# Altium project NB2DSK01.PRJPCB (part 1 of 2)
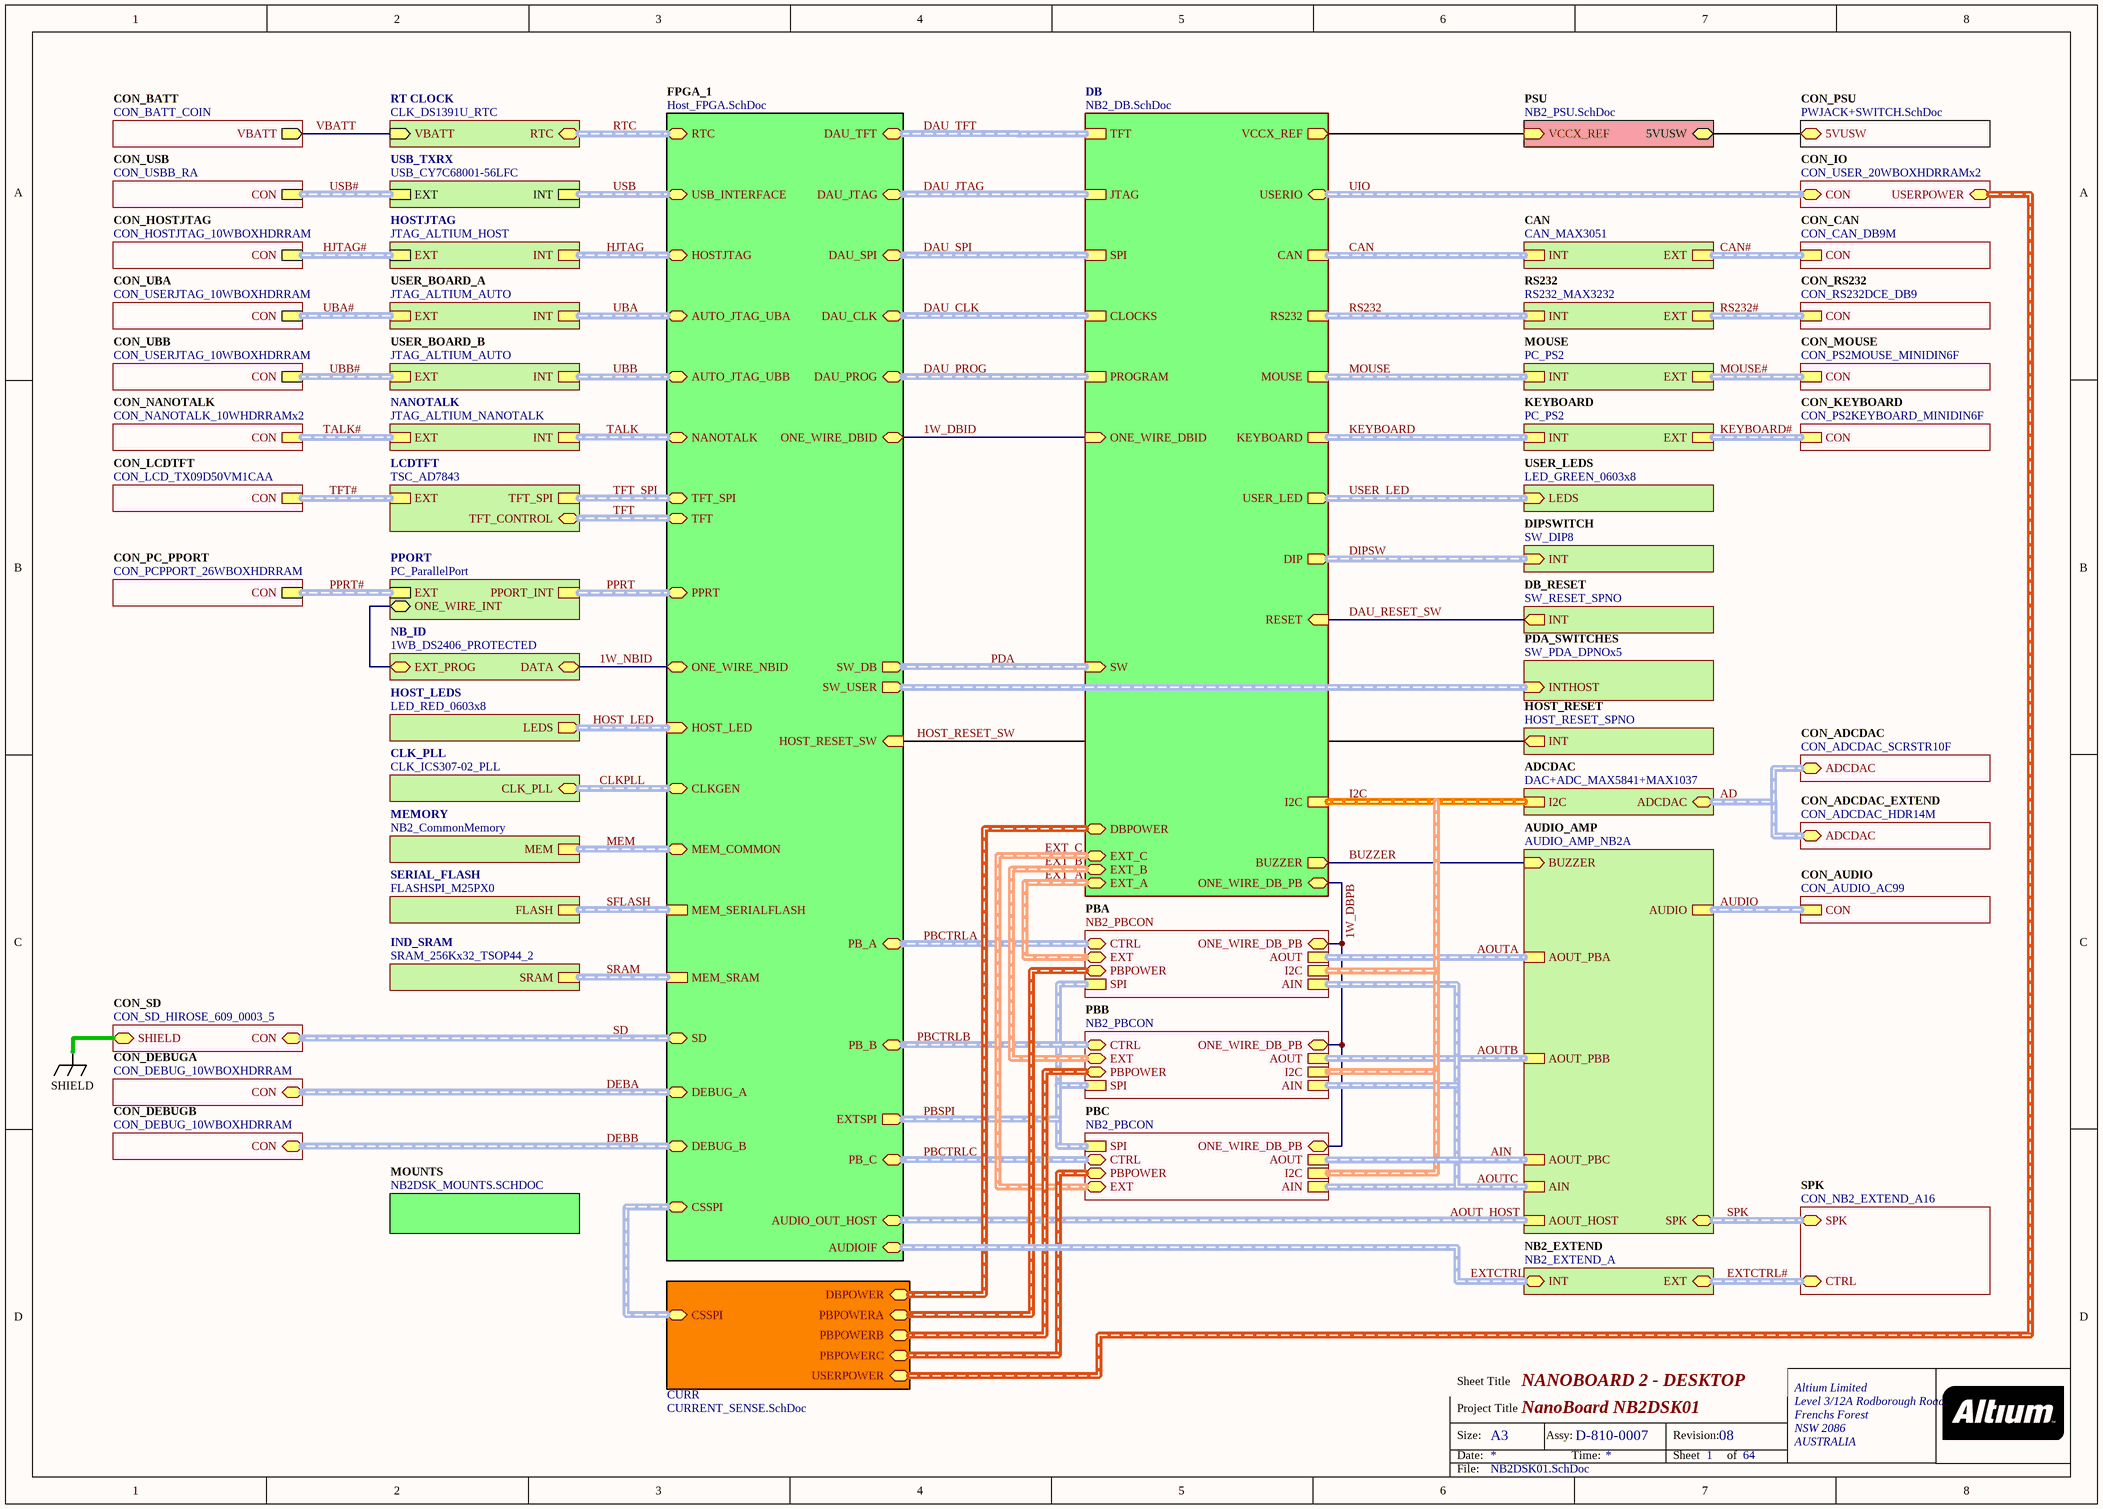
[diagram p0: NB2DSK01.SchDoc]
ProjectAddress1: Level 3/12A Rodborough Road; ProjectAddress2: Frenchs Forest; ProjectAddress3: NSW 2086; ProjectAddress4: AUSTRALIA; ProjectAssyNum: D-810-0007; ProjectOrganization: Altium Limited; ProjectRevision: 08; ProjectTitle: NanoBoard NB2DSK01; ProjectTotalSheets: 64
9 sheets, 136 parts. Net scope: hierarchical (ports join the sheet entries above them; power ports are global).
Board file: NB2DSK01.PcbDoc
Sheets:
  NB2DSK01.SchDoc
    MOUNTS = NB2DSK_Mounts.SchDoc
    PSU = NB2_PSU.SchDoc
    CON_PSU = PWJACK+SWITCH.SchDoc
    FPGA_1 = Host_FPGA.SchDoc
      FPGA_PRGSETUP_1 = FPGA_PRGSETUP.SchDoc
        XC3S1500-4FG676C_CONFIGPWR_1 = XC3S1500-4FG676C_PWRSETUP.SchDoc
    CURR = CURRENT_SENSE.SchDoc
    DB = NB2_DB.SchDoc

## Sheet NB2DSK01.SchDoc: NANOBOARD 2 - DESKTOP
size A3; Organization: Altium Limited.; Address1: Level 3, 12a Rodborough Rd; Address2: Frenchs Forest 2086; Address3: NSW; Address4: AUSTRALIA; DocumentNumber: 1; Revision: 6; SheetNumber: 1; SheetTotal: 64; PageSetup: Record=PageOptions|CenterHorizontal=True|CenterVertical=True|PrintScale=0.67|XCorrection=1.00|YCorrection=1.00|PrintKind=0|BorderSize=5000000|LeftOffset=0|BottomOffset=0|Orientation=1|PaperLength=4200|PaperWidth=2969|Scale=100|PaperSource=7|PrintQuality=1200|MediaType=1|DitherType=10|PaperKind=A4 (210 x 297 mm)|PrintScaleMode=1

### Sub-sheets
ADCDAC = DAC+ADC_MAX5841+MAX1037 (file not in this document): I2C (harness I2C), ADCDAC (harness ADCDAC)
AUDIO_AMP = AUDIO_AMP_NB2A (file not in this document): BUZZER (in), AIN (harness AUDIO_IN), AOUT_PBC (harness AUDIO_OUT), AOUT_PBA (harness AUDIO_OUT), AOUT_PBB (harness AUDIO_OUT), AOUT_HOST (harness AUDIO_OUT), AUDIO (harness AUDIO_EXT), SPK (harness NB2_SPEAKER)
CAN = CAN_MAX3051 (file not in this document): EXT (harness CAN_EXT), INT (harness CAN_INT)
CLK_PLL = CLK_ICS307-02_PLL (file not in this document): CLK_PLL (harness CLK_PLL)
CON_ADCDAC = CON_ADCDAC_SCRSTR10F (file not in this document): ADCDAC (harness ADCDAC)
CON_ADCDAC_EXTEND = CON_ADCDAC_HDR14M (file not in this document): ADCDAC (harness ADCDAC)
CON_AUDIO = CON_AUDIO_AC99 (file not in this document): CON (harness AUDIO_EXT)
CON_BATT = CON_BATT_COIN (file not in this document): VBATT (out)
CON_CAN = CON_CAN_DB9M (file not in this document): CON (harness CAN_EXT)
CON_DEBUGA = CON_DEBUG_10WBOXHDRRAM (file not in this document): CON (harness DBHDR)
CON_DEBUGB = CON_DEBUG_10WBOXHDRRAM (file not in this document): CON (harness DBHDR)
CON_HOSTJTAG = CON_HOSTJTAG_10WBOXHDRRAM (file not in this document): CON (harness HARDSOFT_JTAG)
CON_IO = CON_USER_20WBOXHDRRAMx2 (file not in this document): CON (harness IO36), USERPOWER (harness USERPOWER)
CON_KEYBOARD = CON_PS2KEYBOARD_MINIDIN6F (file not in this document): CON (harness PS2)
CON_LCDTFT = CON_LCD_TX09D50VM1CAA (file not in this document): CON (harness LCD)
CON_MOUSE = CON_PS2MOUSE_MINIDIN6F (file not in this document): CON (harness PS2)
CON_NANOTALK = CON_NANOTALK_10WHDRRAMx2 (file not in this document): CON (harness NANOTALK)
CON_PC_PPORT = CON_PCPPORT_26WBOXHDRRAM (file not in this document): CON (harness PPORT_CON)
CON_PSU = PWJACK+SWITCH.SchDoc: 5VUSW (bidir)
CON_RS232 = CON_RS232DCE_DB9 (file not in this document): CON (harness RS232_EXT)
CON_SD = CON_SD_HIROSE_609_0003_5 (file not in this document): CON (harness SD), SHIELD
CON_UBA = CON_USERJTAG_10WBOXHDRRAM (file not in this document): CON (harness JTAG_CONFIG)
CON_UBB = CON_USERJTAG_10WBOXHDRRAM (file not in this document): CON (harness JTAG_CONFIG)
CON_USB = CON_USBB_RA (file not in this document): CON (harness USB_CON)
CURR = CURRENT_SENSE.SchDoc: PBPOWERA (harness PBPOWER), PBPOWERB (harness PBPOWER), PBPOWERC (harness PBPOWER), DBPOWER (harness DBPOWER), CSSPI (harness CS_SPI), USERPOWER (harness USERPOWER)
DB = NB2_DB.SchDoc: RESET (in), BUZZER (out), DIP (harness SW8), USER_LED (harness LED8), USERIO (harness IO36), VCCX_REF (out), ONE_WIRE_DB_PB (bidir), I2C (harness I2C), CAN (harness CAN_INT), RS232 (harness RS232_INT), KEYBOARD (harness PS2), MOUSE (harness PS2), SW (harness SW5), EXT_A (harness PBIO), EXT_B (harness PBIO), EXT_C (harness PBIO), TFT (harness DAU_TFT), JTAG (harness HardSoft_JTAG), PROGRAM (harness DAU_CTRL), SPI (harness DAU_SPI), CLOCKS (harness DAU_CLK), DBPOWER (harness DBPOWER), ONE_WIRE_DBID (in)
DB_RESET = SW_RESET_SPNO (file not in this document): INT (out)
DIPSWITCH = SW_DIP8 (file not in this document): INT (harness SW8)
FPGA_1 = Host_FPGA.SchDoc: CLKGEN (harness CLK_PLL), HOST_LED (harness LED8), SW_USER (harness SW5), HOST_RESET_SW (in), DEBUG_A (harness DBHDR), DEBUG_B (harness DBHDR), ONE_WIRE_DBID (bidir), ONE_WIRE_NBID (bidir), EXTSPI (harness EXTSPI), PB_A (harness PBCTRL), PB_B (harness PBCTRL), PB_C (harness PBCTRL), AUDIO_OUT_HOST (harness AUDIO_OUT), AUTO_JTAG_UBA (harness JTAG_CONFIG), AUTO_JTAG_UBB (harness JTAG_CONFIG), SD (harness SD), NANOTALK (harness NANOTALK), TFT_SPI (harness TFT_SPI), DAU_TFT (harness DAU_TFT), DAU_JTAG (harness HARDSOFT_JTAG), DAU_PROG (harness DAU_CTRL), DAU_SPI (harness DAU_SPI), DAU_CLK (harness DAU_CLK), MEM_COMMON (harness HOSTMEMORY), USB_INTERFACE (harness USB_INTF), HOSTJTAG (harness HARDSOFT_JTAG), PPRT (harness PPORT_INTF), RTC (harness RTC), MEM_SERIALFLASH (harness SERIALFLASH), MEM_SRAM (harness SRAM_2), CSSPI (harness CS_SPI), AUDIOIF (harness AUDIOIF), SW_DB (harness SW5), TFT (harness TFT)
HOST_LEDS = LED_RED_0603x8 (file not in this document): LEDS (harness LED8)
HOST_RESET = HOST_RESET_SPNO (file not in this document): INT (out)
HOSTJTAG = JTAG_ALTIUM_HOST (file not in this document): EXT (harness HARDSOFT_JTAG), INT (harness HARDSOFT_JTAG)
IND_SRAM = SRAM_256Kx32_TSOP44_2 (file not in this document): SRAM (harness SRAM_2)
KEYBOARD = PC_PS2 (file not in this document): EXT (harness PS2), INT (harness PS2)
LCDTFT = TSC_AD7843 (file not in this document): EXT (harness LCD), TFT_SPI (harness TFT_SPI), TFT_CONTROL (harness TFT)
MEMORY = NB2_CommonMemory (file not in this document): MEM (harness HOSTMEMORY)
MOUNTS = NB2DSK_MOUNTS.SCHDOC: no entries
MOUSE = PC_PS2 (file not in this document): EXT (harness PS2), INT (harness PS2)
NANOTALK = JTAG_ALTIUM_NANOTALK (file not in this document): EXT (harness NANOTALK), INT (harness NANOTALK)
NB2_EXTEND = NB2_EXTEND_A (file not in this document): INT (harness AUDIOIF), EXT (harness AUDIOIF)
NB_ID = 1WB_DS2406_PROTECTED (file not in this document): DATA (bidir), EXT_PROG (bidir)
PBA = NB2_PBCON (file not in this document): EXT (harness PBIO), ONE_WIRE_DB_PB (bidir), AIN (harness AUDIO_IN), I2C (harness I2C), SPI (harness EXTSPI), AOUT (harness AUDIO_OUT), CTRL (harness PBCTRL), PBPOWER (harness PBPOWER)
PBB = NB2_PBCON (file not in this document): EXT (harness PBIO), ONE_WIRE_DB_PB (bidir), AIN (harness AUDIO_IN), I2C (harness I2C), SPI (harness EXTSPI), AOUT (harness AUDIO_OUT), CTRL (harness PBCTRL), PBPOWER (harness PBPOWER)
PBC = NB2_PBCON (file not in this document): EXT, ONE_WIRE_DB_PB (bidir), AIN (harness AUDIO_IN), I2C (harness I2C), SPI (harness EXTSPI), AOUT (harness AUDIO_OUT), CTRL (harness PBCTRL), PBPOWER (harness PBPOWER)
PDA_SWITCHES = SW_PDA_DPNOx5 (file not in this document): INTHOST (harness SW5)
PPORT = PC_ParallelPort (file not in this document): PPORT_INT (harness PPORT_INTF), EXT (harness PPORT_CON), ONE_WIRE_INT (bidir)
PSU = NB2_PSU.SchDoc: VCCX_REF (in), 5VUSW (bidir)
RS232 = RS232_MAX3232 (file not in this document): INT (harness RS232_INT), EXT (harness RS232_EXT)
RT CLOCK = CLK_DS1391U_RTC (file not in this document): VBATT (in), RTC (harness RTC)
SERIAL_FLASH = FLASHSPI_M25PX0 (file not in this document): FLASH (harness SERIALFLASH)
SPK = CON_NB2_EXTEND_A16 (file not in this document): CTRL (harness AUDIOIF), SPK (harness NB2_SPEAKER)
USB_TXRX = USB_CY7C68001-56LFC (file not in this document): EXT (harness USB_CON), INT (harness USB_INTF)
USER_BOARD_A = JTAG_ALTIUM_AUTO (file not in this document): EXT (harness JTAG_CONFIG), INT (harness JTAG_CONFIG)
USER_BOARD_B = JTAG_ALTIUM_AUTO (file not in this document): EXT (harness JTAG_CONFIG), INT (harness JTAG_CONFIG)
USER_LEDS = LED_GREEN_0603x8 (file not in this document): LEDS (harness LED8)

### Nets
1W_DBID: sheet FPGA_1/ONE_WIRE_DBID, sheet DB/ONE_WIRE_DBID
1W_DBPB: sheet PBA/ONE_WIRE_DB_PB, sheet PBC/ONE_WIRE_DB_PB, sheet PBB/ONE_WIRE_DB_PB, sheet DB/ONE_WIRE_DB_PB
1W_NBID: sheet FPGA_1/ONE_WIRE_NBID, sheet NB_ID/DATA
5VUSW: sheet PSU/5VUSW, sheet CON_PSU/5VUSW
BUZZER: sheet AUDIO_AMP/BUZZER, sheet DB/BUZZER
DAU_RESET_SW: sheet DB_RESET/INT, sheet DB/RESET
HOST_RESET_SW: sheet FPGA_1/HOST_RESET_SW, sheet HOST_RESET/INT
VBATT: sheet CON_BATT/VBATT, sheet RT CLOCK/VBATT
VCCX_REF: sheet PSU/VCCX_REF, sheet DB/VCCX_REF
(unnamed): sheet PPORT/ONE_WIRE_INT, sheet NB_ID/EXT_PROG

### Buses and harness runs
harness AD = sheet ADCDAC/ADCDAC = sheet CON_ADCDAC/ADCDAC = sheet CON_ADCDAC_EXTEND/ADCDAC
harness AIN = sheet AUDIO_AMP/AOUT_PBC = sheet PBC/AOUT
harness AOUT_HOST = sheet AUDIO_AMP/AOUT_HOST = sheet FPGA_1/AUDIO_OUT_HOST
harness AOUTA = sheet AUDIO_AMP/AOUT_PBA = sheet PBA/AOUT
harness AOUTB = sheet AUDIO_AMP/AOUT_PBB = sheet PBB/AOUT
harness AOUTC = sheet AUDIO_AMP/AIN = sheet PBA/AIN = sheet PBB/AIN = sheet PBC/AIN
harness AUDIO = sheet AUDIO_AMP/AUDIO = sheet CON_AUDIO/CON
harness CAN = sheet CAN/INT = sheet DB/CAN
harness CAN# = sheet CAN/EXT = sheet CON_CAN/CON
harness CLKPLL = sheet CLK_PLL/CLK_PLL = sheet FPGA_1/CLKGEN
harness DAU_CLK = sheet DB/CLOCKS = sheet FPGA_1/DAU_CLK
harness DAU_JTAG = sheet DB/JTAG = sheet FPGA_1/DAU_JTAG
harness DAU_PROG = sheet DB/PROGRAM = sheet FPGA_1/DAU_PROG
harness DAU_SPI = sheet DB/SPI = sheet FPGA_1/DAU_SPI
harness DAU_TFT = sheet DB/TFT = sheet FPGA_1/DAU_TFT
harness DEBA = sheet CON_DEBUGA/CON = sheet FPGA_1/DEBUG_A
harness DEBB = sheet CON_DEBUGB/CON = sheet FPGA_1/DEBUG_B
harness DIPSW = sheet DB/DIP = sheet DIPSWITCH/INT
harness EXT_A = sheet DB/EXT_A = sheet PBA/EXT
harness EXT_B = sheet DB/EXT_B = sheet PBB/EXT
harness EXT_C = sheet DB/EXT_C = sheet PBC/EXT
harness EXTCTRL = sheet FPGA_1/AUDIOIF = sheet NB2_EXTEND/INT
harness EXTCTRL# = sheet NB2_EXTEND/EXT = sheet SPK/CTRL
harness HJTAG = sheet FPGA_1/HOSTJTAG = sheet HOSTJTAG/INT
harness HJTAG# = sheet CON_HOSTJTAG/CON = sheet HOSTJTAG/EXT
harness HOST_LED = sheet FPGA_1/HOST_LED = sheet HOST_LEDS/LEDS
harness I2C = sheet ADCDAC/I2C = sheet DB/I2C = sheet PBA/I2C = sheet PBB/I2C = sheet PBC/I2C
harness KEYBOARD = sheet DB/KEYBOARD = sheet KEYBOARD/INT
harness KEYBOARD# = sheet CON_KEYBOARD/CON = sheet KEYBOARD/EXT
harness MEM = sheet FPGA_1/MEM_COMMON = sheet MEMORY/MEM
harness MOUSE = sheet DB/MOUSE = sheet MOUSE/INT
harness MOUSE# = sheet CON_MOUSE/CON = sheet MOUSE/EXT
harness PBCTRLA = sheet FPGA_1/PB_A = sheet PBA/CTRL
harness PBCTRLB = sheet FPGA_1/PB_B = sheet PBB/CTRL
harness PBCTRLC = sheet FPGA_1/PB_C = sheet PBC/CTRL
harness PBSPI = sheet FPGA_1/EXTSPI = sheet PBA/SPI = sheet PBB/SPI = sheet PBC/SPI
harness PDA = sheet DB/SW = sheet FPGA_1/SW_DB
harness PPRT = sheet FPGA_1/PPRT = sheet PPORT/PPORT_INT
harness PPRT# = sheet CON_PC_PPORT/CON = sheet PPORT/EXT
harness RS232 = sheet DB/RS232 = sheet RS232/INT
harness RS232# = sheet CON_RS232/CON = sheet RS232/EXT
harness RTC = sheet FPGA_1/RTC = sheet RT CLOCK/RTC
harness SD = sheet CON_SD/CON = sheet FPGA_1/SD
harness SFLASH = sheet FPGA_1/MEM_SERIALFLASH = sheet SERIAL_FLASH/FLASH
harness sheet CON_IO/USERPOWER = sheet CURR/USERPOWER
harness sheet CURR/CSSPI = sheet FPGA_1/CSSPI
harness sheet CURR/DBPOWER = sheet DB/DBPOWER
harness sheet CURR/PBPOWERA = sheet PBA/PBPOWER
harness sheet CURR/PBPOWERB = sheet PBB/PBPOWER
harness sheet CURR/PBPOWERC = sheet PBC/PBPOWER
harness sheet FPGA_1/SW_USER = sheet PDA_SWITCHES/INTHOST
harness SPK = sheet AUDIO_AMP/SPK = sheet SPK/SPK
harness SRAM = sheet FPGA_1/MEM_SRAM = sheet IND_SRAM/SRAM
harness TALK = sheet FPGA_1/NANOTALK = sheet NANOTALK/INT
harness TALK# = sheet CON_NANOTALK/CON = sheet NANOTALK/EXT
harness TFT = sheet FPGA_1/TFT = sheet LCDTFT/TFT_CONTROL
harness TFT# = sheet CON_LCDTFT/CON = sheet LCDTFT/EXT
harness TFT_SPI = sheet FPGA_1/TFT_SPI = sheet LCDTFT/TFT_SPI
harness UBA = sheet FPGA_1/AUTO_JTAG_UBA = sheet USER_BOARD_A/INT
harness UBA# = sheet CON_UBA/CON = sheet USER_BOARD_A/EXT
harness UBB = sheet FPGA_1/AUTO_JTAG_UBB = sheet USER_BOARD_B/INT
harness UBB# = sheet CON_UBB/CON = sheet USER_BOARD_B/EXT
harness UIO = sheet CON_IO/CON = sheet DB/USERIO
harness USB = sheet FPGA_1/USB_INTERFACE = sheet USB_TXRX/INT
harness USB# = sheet CON_USB/CON = sheet USB_TXRX/EXT
harness USER_LED = sheet DB/USER_LED = sheet USER_LEDS/LEDS

## Sheet NB2DSK_Mounts.SchDoc: NB2DSK01 Holes and Graphics
size A4; Organization: Altium Limited.; Address1: Level 3, 12a Rodborough Rd; Address2: Frenchs Forest 2086; Address3: NSW; Address4: AUSTRALIA; DocumentNumber: 38; Revision: 6; SheetNumber: 38; SheetTotal: 64
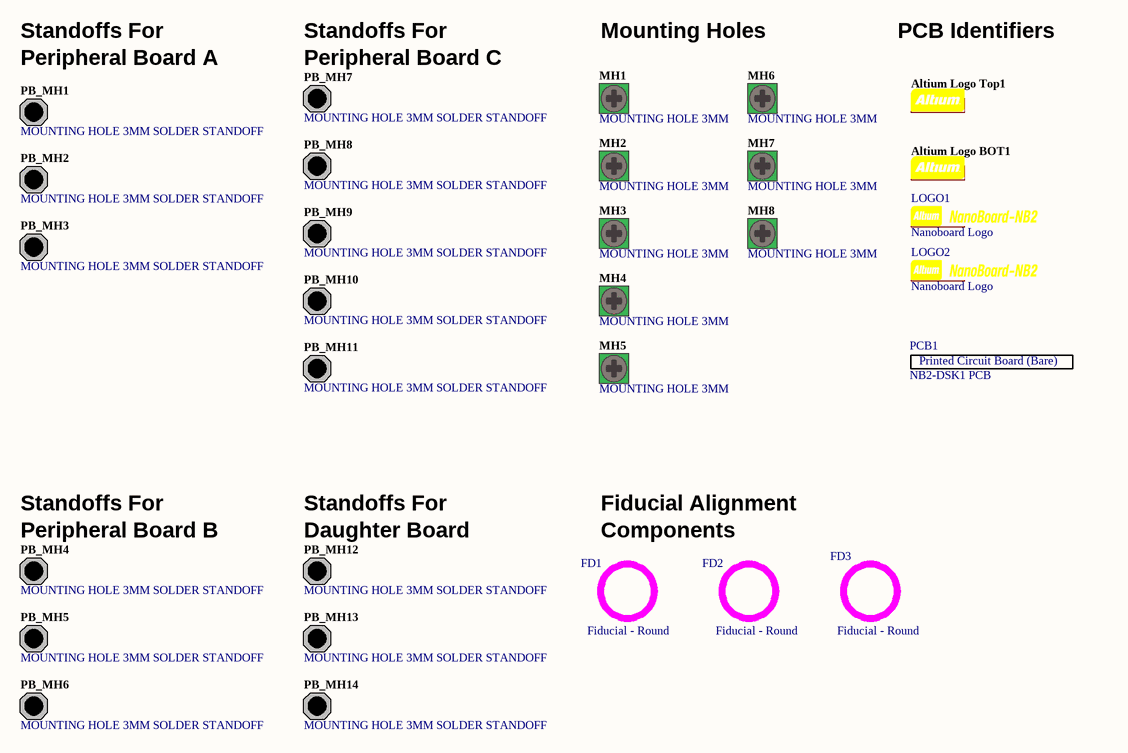
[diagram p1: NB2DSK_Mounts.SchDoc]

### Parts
Altium_Logo_BOT1  Altium  [Logo-Altium]  (value not drawn)  (no BOM)
Altium_Logo_Top1  Altium  [Logo-Altium]  (value not drawn)  (no BOM)
FD1  Fiducial - Round  [FIDUCIAL ROUND]
FD2  Fiducial - Round  [FIDUCIAL ROUND]
FD3  Fiducial - Round  [FIDUCIAL ROUND]
LOGO1  Nanoboard Logo  [NANOBOARD LOGO]  (no BOM)
LOGO2  Nanoboard Logo  [NANOBOARD LOGO]  (no BOM)
MH1  MOUNTING HOLE 3MM  [MOUNTING_HOLE_3MM]  (no BOM)
MH2  MOUNTING HOLE 3MM  [MOUNTING_HOLE_3MM]  (no BOM)
MH3  MOUNTING HOLE 3MM  [MOUNTING_HOLE_3MM]  (no BOM)
MH4  MOUNTING HOLE 3MM  [MOUNTING_HOLE_3MM]  (no BOM)
MH5  MOUNTING HOLE 3MM  [MOUNTING_HOLE_3MM]  (no BOM)
MH6  MOUNTING HOLE 3MM  [MOUNTING_HOLE_3MM]  (no BOM)
MH7  MOUNTING HOLE 3MM  [MOUNTING_HOLE_3MM]  (no BOM)
MH8  MOUNTING HOLE 3MM  [MOUNTING_HOLE_3MM]  (no BOM)
PB_MH1  MOUNTING HOLE 3MM SOLDER STANDOFF  [STANDOFF_SOLDER_3MM]  (no BOM)
PB_MH2  MOUNTING HOLE 3MM SOLDER STANDOFF  [STANDOFF_SOLDER_3MM]  (no BOM)
PB_MH3  MOUNTING HOLE 3MM SOLDER STANDOFF  [STANDOFF_SOLDER_3MM]  (no BOM)
PB_MH4  MOUNTING HOLE 3MM SOLDER STANDOFF  [STANDOFF_SOLDER_3MM]  (no BOM)
PB_MH5  MOUNTING HOLE 3MM SOLDER STANDOFF  [STANDOFF_SOLDER_3MM]  (no BOM)
PB_MH6  MOUNTING HOLE 3MM SOLDER STANDOFF  [STANDOFF_SOLDER_3MM]  (no BOM)
PB_MH7  MOUNTING HOLE 3MM SOLDER STANDOFF  [STANDOFF_SOLDER_3MM]  (no BOM)
PB_MH8  MOUNTING HOLE 3MM SOLDER STANDOFF  [STANDOFF_SOLDER_3MM]  (no BOM)
PB_MH9  MOUNTING HOLE 3MM SOLDER STANDOFF  [STANDOFF_SOLDER_3MM]  (no BOM)
PB_MH10  MOUNTING HOLE 3MM SOLDER STANDOFF  [STANDOFF_SOLDER_3MM]  (no BOM)
PB_MH11  MOUNTING HOLE 3MM SOLDER STANDOFF  [STANDOFF_SOLDER_3MM]  (no BOM)
PB_MH12  MOUNTING HOLE 3MM SOLDER STANDOFF  [STANDOFF_SOLDER_3MM]  (no BOM)
PB_MH13  MOUNTING HOLE 3MM SOLDER STANDOFF  [STANDOFF_SOLDER_3MM]  (no BOM)
PB_MH14  MOUNTING HOLE 3MM SOLDER STANDOFF  [STANDOFF_SOLDER_3MM]  (no BOM)
PCB1  NB2-DSK1 PCB

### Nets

Not connected (* = marked no-connect by the designer): MH1 1; MH2 1; MH3 1; MH4 1; MH5 1; MH6 1; MH7 1; MH8 1; PB_MH1 1; PB_MH2 1; PB_MH3 1; PB_MH4 1; PB_MH5 1; PB_MH6 1; PB_MH7 1; PB_MH8 1; PB_MH9 1; PB_MH10 1; PB_MH11 1; PB_MH12 1; PB_MH13 1; PB_MH14 1

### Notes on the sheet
- Standoffs For
- Mounting Holes
- PCB Identifiers
- (near PB_MH1) Peripheral Board A
- (near PB_MH7) Peripheral Board C
- Fiducial Alignment
- (near PB_MH4) Peripheral Board B
- (near PB_MH12) Daughter Board
- Components

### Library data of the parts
Altium_Logo_BOT1 Altium_Logo_Top1 = D-000-0003: Altium Logo for PCB
FD1-FD3 = D-004-0001: Fiducial - Round 1.5mm Top-Bottom
LOGO1 LOGO2 = D-000-0000
MH1-MH8 = D-001-0001: Mounting Hole, M3 Screw, Plated, Square Pad
PB_MH1-PB_MH14 = D-001-0006: Mounting Hole for Solder Standoff, M3 Screw, Plated, Round Pad
PCB1 = D-000-0014: PCB, NB2 Desktop (NB2-DSK1)

## Sheet NB2_PSU.SchDoc: NB2DSK01 POWER SUPPLIES
size A4; Organization: Altium Limited.; Address1: Level 3, 12a Rodborough Rd; Address2: Frenchs Forest 2086; Address3: NSW; Address4: AUSTRALIA; DocumentNumber: 29; Revision: 6; SheetNumber: 29; SheetTotal: 64
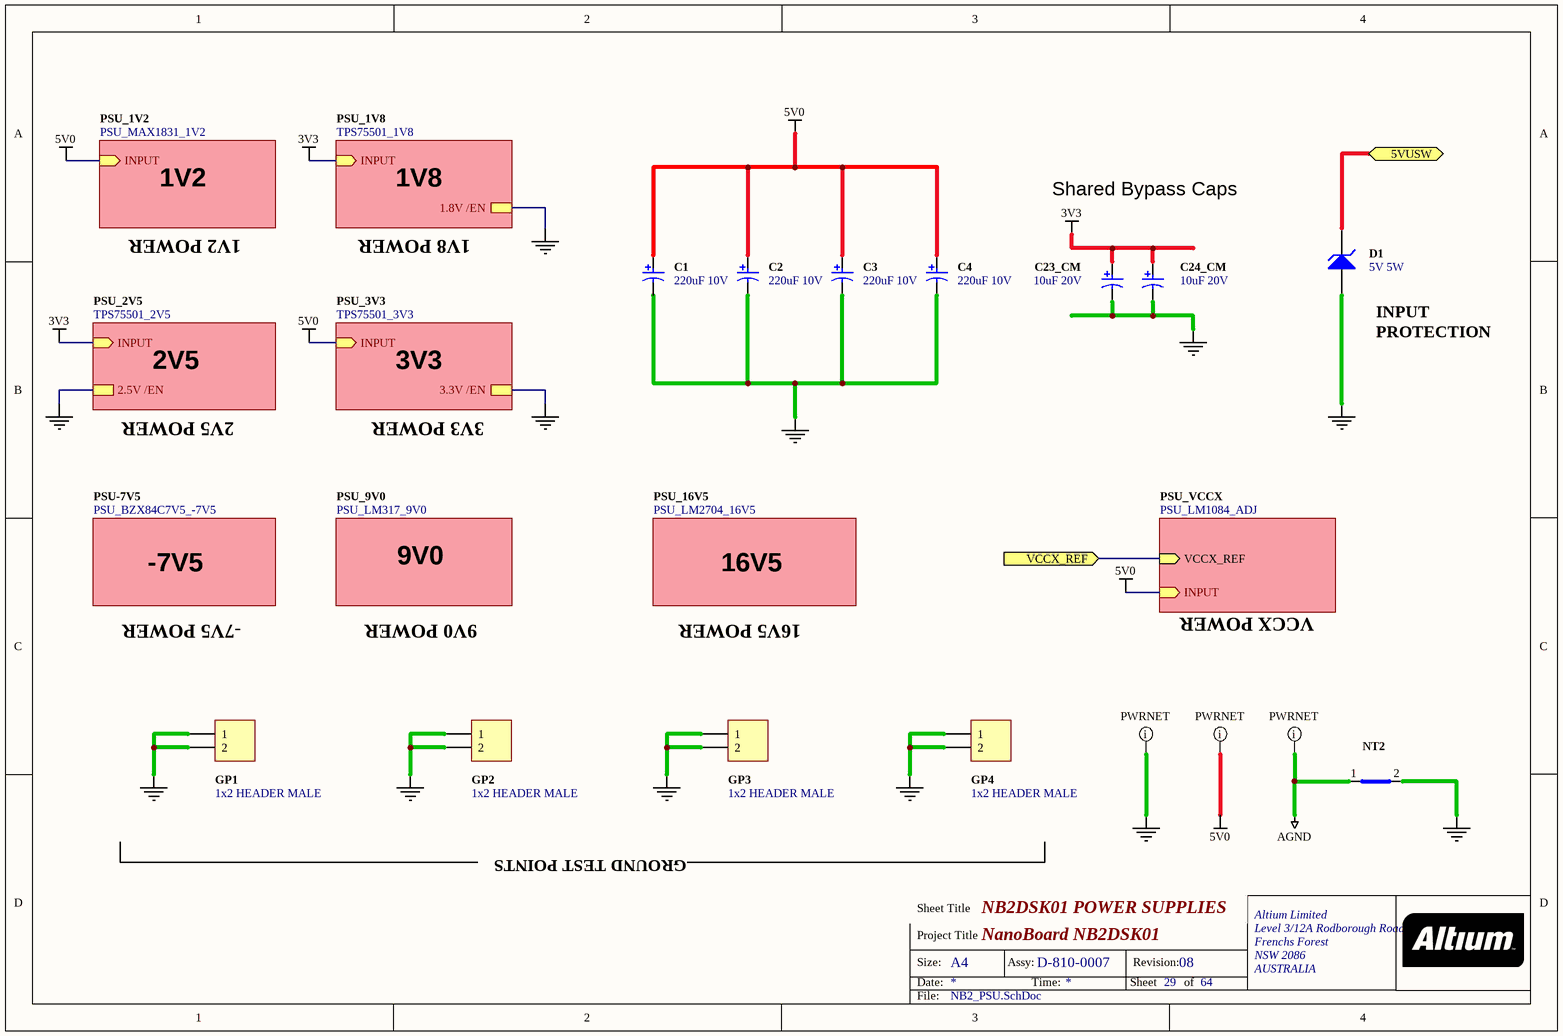
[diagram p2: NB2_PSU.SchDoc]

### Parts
C1  220uF 10V  [CAPC7343-STAR]
C2  220uF 10V  [CAPC7343-STAR]
C3  220uF 10V  [CAPC7343-STAR]
C4  220uF 10V  [CAPC7343-STAR]
C23_CM  10uF 20V  [CAPC3528-STAR]
C24_CM  10uF 20V  [CAPC3528-STAR]
D1  5V 5W  [DIOM8059]
GP1  1x2 HEADER MALE  [HDR1X2]
GP2  1x2 HEADER MALE  [HDR1X2]
GP3  1x2 HEADER MALE  [HDR1X2]
GP4  1x2 HEADER MALE  [HDR1X2]
NT2  Net Tie SMT2  [NETTIE-SMT2-31X51]  (value not drawn)  (net tie, no BOM)

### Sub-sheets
PSU-7V5 = PSU_BZX84C7V5_-7V5 (file not in this document): no entries
PSU_1V2 = PSU_MAX1831_1V2 (file not in this document): INPUT (in)
PSU_1V8 = TPS75501_1V8 (file not in this document): 1.8V /EN, INPUT (in)
PSU_2V5 = TPS75501_2V5 (file not in this document): 2.5V /EN, INPUT (in)
PSU_3V3 = TPS75501_3V3 (file not in this document): 3.3V /EN, INPUT (in)
PSU_9V0 = PSU_LM317_9V0 (file not in this document): no entries
PSU_16V5 = PSU_LM2704_16V5 (file not in this document): no entries
PSU_VCCX = PSU_LM1084_ADJ (file not in this document): VCCX_REF (in), INPUT (in)

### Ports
5VUSW, VCCX_REF (in)

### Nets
3V3: C23_CM.1 C24_CM.1 ; sheet PSU_2V5/INPUT, sheet PSU_1V8/INPUT
5V0: C1.1 C2.1 C3.1 C4.1 ; sheet PSU_3V3/INPUT, sheet PSU_1V2/INPUT, sheet PSU_VCCX/INPUT
AGND: NT2.1(Net1)
GND: C1.2 C2.2 C3.2 C4.2 C23_CM.2 C24_CM.2 D1.1(A) GP1.1 GP1.2 GP2.1 GP2.2 GP3.1 GP3.2 GP4.1 GP4.2 NT2.2(Net2) ; sheet PSU_3V3/3.3V /EN, sheet PSU_2V5/2.5V /EN, sheet PSU_1V8/1.8V /EN
5VUSW: D1.2(K) ; port 5VUSW
VCCX_REF: port VCCX_REF, sheet PSU_VCCX/VCCX_REF

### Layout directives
net class PWRNET: 5V0, AGND, GND

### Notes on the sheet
- 1V2
- 1V2 POWER
- 1V8
- 1V8 POWER
- Shared Bypass Caps
- 2V5
- 3V3
- (near D1) INPUT
- PROTECTION
- 2V5 POWER
- 3V3 POWER
- -7V5
- 9V0
- 16V5
- -7V5 POWER
- 9V0 POWER
- 16V5 POWER
- VCCX POWER
- GROUND TEST POINTS

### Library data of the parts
C1-C4 = D-101-0088: Capacitor, Tantalum, 220uF 10% 10V MCCT-D (7343-31); Polarity: Polarized
C23_CM C24_CM = D-101-0007: Capacitor, Tantalum, 10uF 10% 20V MCCT-B (3528); Polarity: Polarized
D1 = D-150-0001: Zener Diode, 5V 5W; Max Forward Current: mA; Rated Voltage: mV
GP1-GP4 = D-300-0020: Header IDC, 2 x 1 Pin Vertical 2.54mm Pitch (Non-Boxed, Male); Max Current: 3 A
NT2 = D-002-0003: Net-Tie, Surface Mount, 2 x 1.6mm x 0.8mm SMT Pads - For 0.8mm Track

## Sheet PWJACK+SWITCH.SchDoc: Power Jack & Switch
size A4; Organization: Altium Limited.; Address1: Level 3, 12a Rodborough Rd; Address2: Frenchs Forest 2086; Address3: NSW; Address4: AUSTRALIA; DocumentNumber: 62; Revision: 6; SheetNumber: 62; SheetTotal: 64
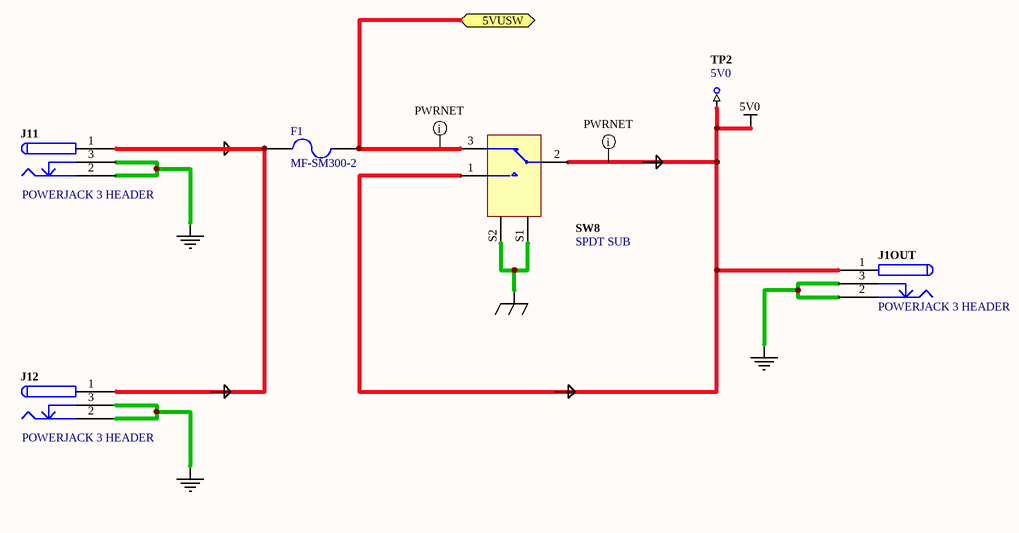
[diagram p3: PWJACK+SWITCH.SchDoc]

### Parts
(Parts that share a designator on the sheet are numbered #1, #2 ... from top to bottom, then left to right.)
F1  MF-SM300-2  [MF_SM250]
J1OUT  POWERJACK 3 HEADER  [KLD-0202]
J11  POWERJACK 3 HEADER  [KLD-0202]
J12  POWERJACK 3 HEADER  [KLD-0202]
SW8  SPDT SUB  [T8019L-TNQ]
TP2#1  5V0  [TestPin]  (no BOM)

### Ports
5VUSW

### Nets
5V0: J1OUT.1 SW8.1 SW8.2 TP2#1.1
GND: J1OUT.2 J1OUT.3 J11.2 J11.3 J12.2 J12.3
SHIELD: SW8.S1 SW8.S2
5VUSW: F1.2 SW8.3 ; port 5VUSW
NetF1_1: F1.1 J11.1 J12.1

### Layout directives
net class PWRNET: 5V0, 5VUSW

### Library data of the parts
F1 = D-106-0002: Mutifuse, SMD 8A; Amperage: 5 A; Rated Voltage: mV
J1OUT J11 J12 = D-300-0007: Connector, 3 Conductor Power Jack 2 break 2 aux contacts
SW8 = D-301-0000: Switch, SPDT Subminiature Toggle
TP2#1 = D-006-0000: Test Point, PCB Mount with Silkscreen Box

## Sheet Host_FPGA.SchDoc: Host Controller - Spartan3-1500
size A2; Organization: Altium Limited.; Address1: Level 3, 12a Rodborough Rd; Address2: Frenchs Forest 2086; Address3: NSW; Address4: AUSTRALIA; DocumentNumber: 12; Revision: 6; SheetNumber: 12; SheetTotal: 64; PageSetup: Record=PageOptions|CenterHorizontal=True|CenterVertical=True|PrintScale=0.47|XCorrection=1.00|YCorrection=1.00|PrintKind=0|BorderSize=5000000|LeftOffset=0|BottomOffset=0|Orientation=2|PaperLength=1000|PaperWidth=1000|Scale=100|PaperSource=7|PrintQuality=1200|MediaType=1|DitherType=10|PaperKind=A4 (210 x 297 mm)|PrintScaleMode=1
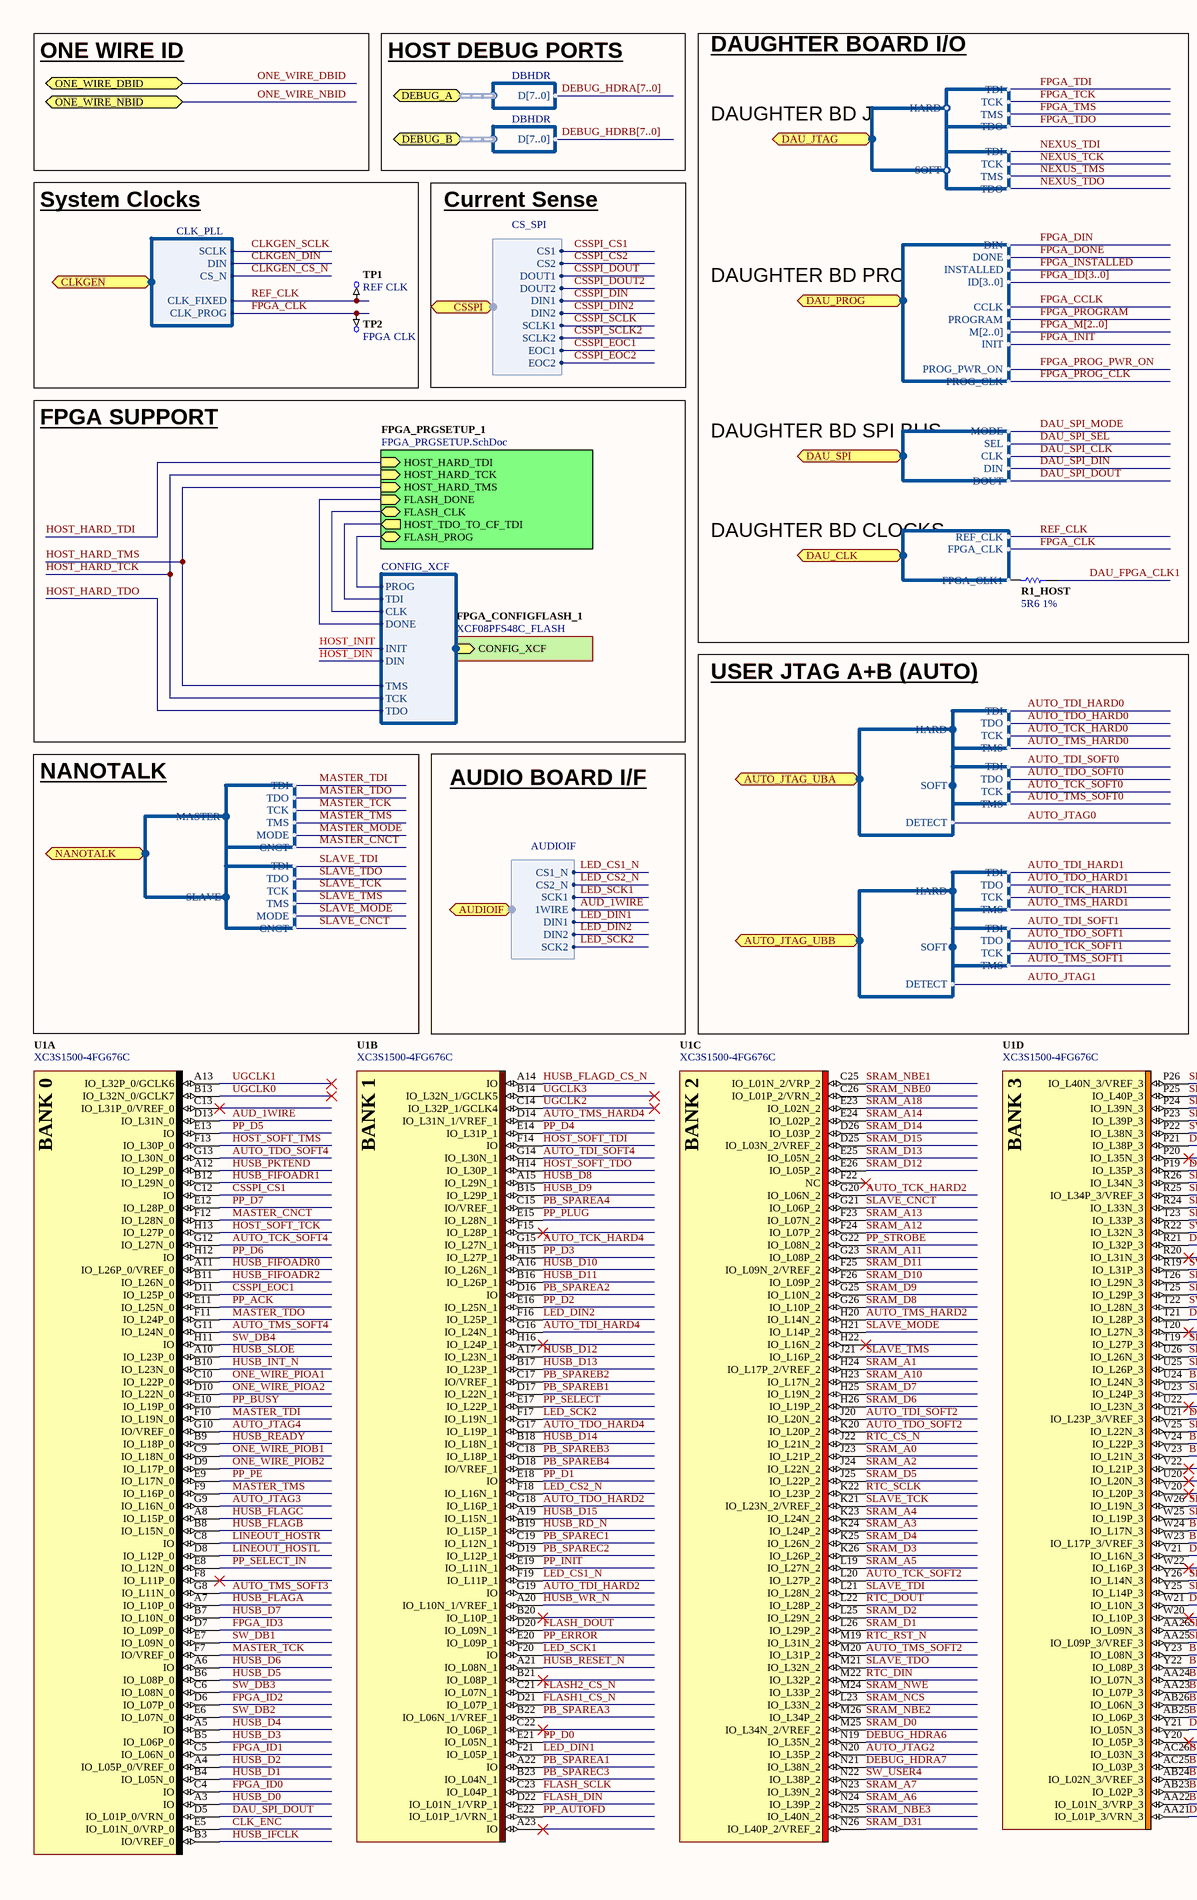
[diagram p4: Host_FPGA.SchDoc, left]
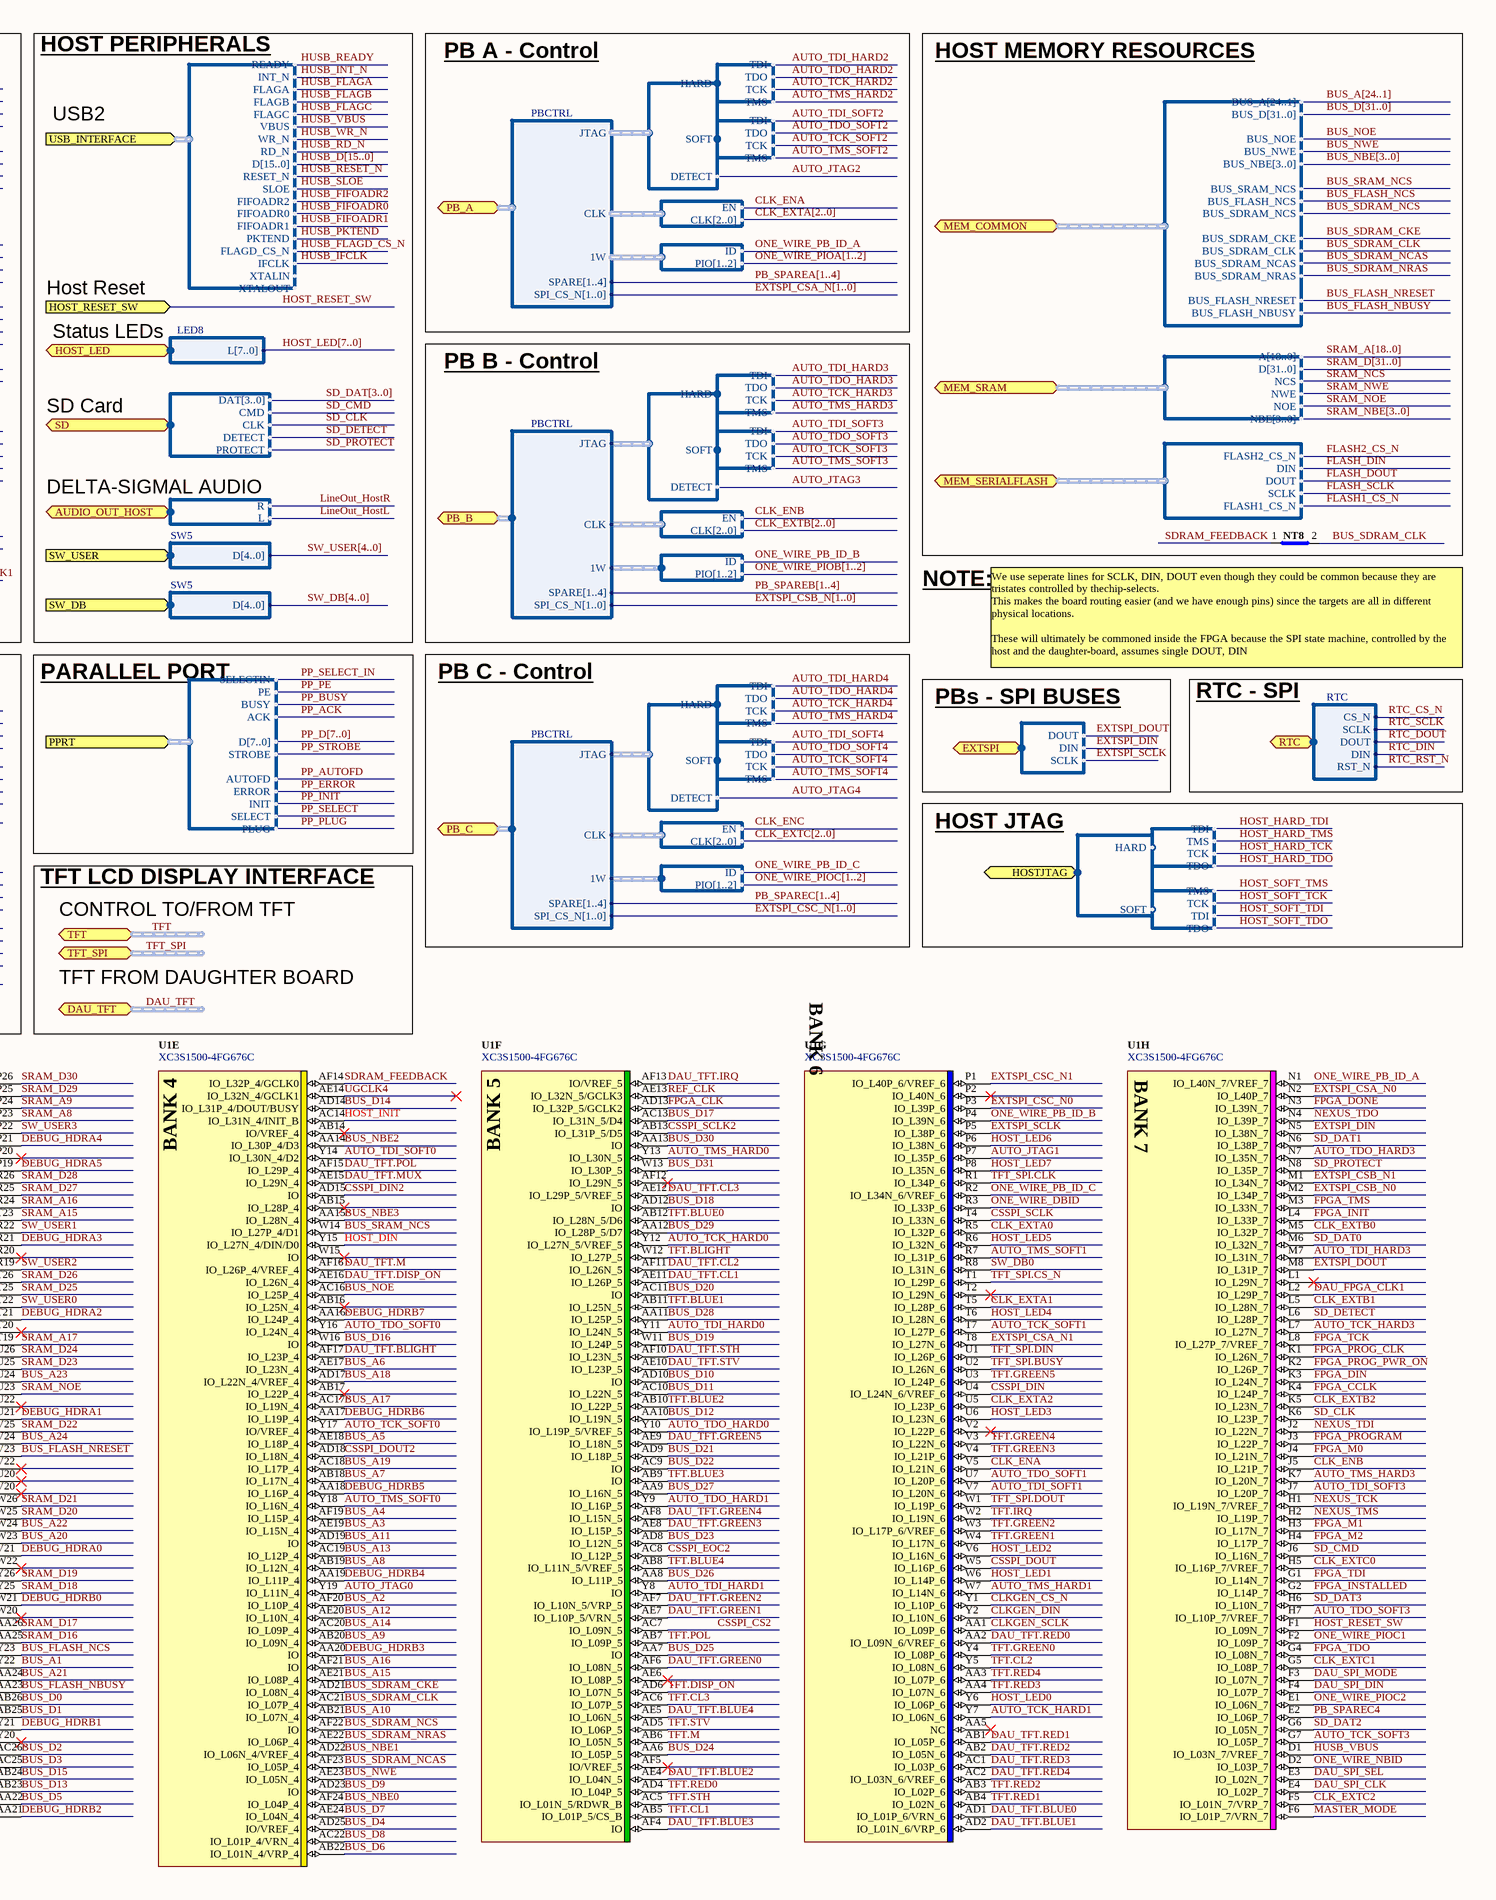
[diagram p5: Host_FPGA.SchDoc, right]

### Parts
(Parts that share a designator on the sheet are numbered #1, #2 ... from top to bottom, then left to right.)
NT8  Net Tie SMT2  [NETTIE-SMT2-8X8]  (value not drawn)  (net tie, no BOM)
R1_HOST  5R6 1%  [RESC1005-STAR]
TP1  REF CLK  [TestPin]  (no BOM)
TP2#2  FPGA CLK  [TestPin]  (no BOM)
U1#1  XC3S1500-4FG676C  [BGA100P26X26-676]  (parts A,B,C,D,E,F,G,H of 12)

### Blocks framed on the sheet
DAUGHTER BOARD I/O: R1_HOST
HOST MEMORY RESOURCES: NT8
System Clocks: TP1 TP2#2

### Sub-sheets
FPGA_CONFIGFLASH_1 = XCF08PFS48C_FLASH (file not in this document): CONFIG_XCF (harness CONFIG_XCF)
FPGA_PRGSETUP_1 = FPGA_PRGSETUP.SchDoc: HOST_HARD_TMS (in), HOST_HARD_TDI (in), HOST_HARD_TCK (in), HOST_TDO_TO_CF_TDI (out), FLASH_PROG (bidir), FLASH_CLK (bidir), FLASH_DONE (in)

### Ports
AUDIO_OUT_HOST (harness AUDIO_OUT), AUDIOIF (harness AUDIOIF), AUTO_JTAG_UBA (harness JTAG_CONFIG), AUTO_JTAG_UBB (harness JTAG_CONFIG), CLKGEN (harness CLK_PLL), CSSPI (harness CS_SPI), DAU_CLK (harness DAU_CLK), DAU_JTAG (harness HARDSOFT_JTAG), DAU_PROG (harness DAU_CTRL), DAU_SPI (harness DAU_SPI), DAU_TFT (harness DAU_TFT), DEBUG_A (harness DBHDR), DEBUG_B (harness DBHDR), EXTSPI (harness EXTSPI), HOST_LED (harness LED8), HOST_RESET_SW (in), HOSTJTAG (harness HARDSOFT_JTAG), MEM_COMMON (harness HOSTMEMORY), MEM_SERIALFLASH (harness SERIALFLASH), MEM_SRAM (harness SRAM_2), NANOTALK (harness NANOTALK), ONE_WIRE_DBID (bidir), ONE_WIRE_NBID (bidir), PB_A (harness PBCTRL), PB_B (harness PBCTRL), PB_C (harness PBCTRL), PPRT (harness PPORT_INTF), RTC (harness RTC), SD (harness SD), SW_DB (harness SW5), SW_USER (harness SW5), TFT (harness TFT), TFT_SPI (harness TFT_SPI), USB_INTERFACE (harness USB_INTF)

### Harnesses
SERIALFLASH: FLASH2_CS_N, DIN, DOUT, SCLK, FLASH1_CS_N
SRAM_2: A[18..0], D[31..0], NCS, NWE, NOE, NBE[3..0]
HOSTMEMORY: BUS_A[24..1], BUS_D[31..0], BUS_NOE, BUS_NWE, BUS_NBE[3..0], BUS_SRAM_NCS, BUS_FLASH_NCS, BUS_SDRAM_NCS, BUS_SDRAM_CKE, BUS_SDRAM_CLK, BUS_SDRAM_NCAS, BUS_SDRAM_NRAS, BUS_FLASH_NRESET, BUS_FLASH_NBUSY
DAU_CLK: REF_CLK, FPGA_CLK, FPGA_CLK1
DAU_SPI: MODE, SEL, CLK, DIN, DOUT
DAU_CTRL: DIN, DONE, INSTALLED, ID[3..0], CCLK, PROGRAM, M[2..0], INIT, PROG_PWR_ON, PROG_CLK
JTAG: TMS, TDO, TDI, TCK
HARDSOFT_JTAG: HARD, SOFT
NANOTALK: MASTER, SLAVE
NANOTALK_JTAG: TDI, TCK, TMS, TDO, MODE, CNCT
SD: DAT[3..0], CMD, CLK, DETECT, PROTECT
JTAG_CONFIG: HARD, SOFT, DETECT
JTAG: TDI, TDO, TCK, TMS
AUDIO_OUT: R, L
EXTSPI: DOUT, DIN, SCLK
GATE_CLOCKS: EN, CLK[2..0]
ONE_WIRE: ID, PIO[1..2]
PPORT_INTF: SELECTIN, PE, BUSY, ACK, STROBE, AUTOFD, ERROR, INIT, SELECT, PLUG, D[7..0]
USB_INTF: READY, INT_N, SLOE, FIFOADR2, FIFOADR0, FIFOADR1, PKTEND, FLAGD_CS_N, FLAGA, FLAGB, FLAGC, WR_N, RD_N, D[15..0], RESET_N, IFCLK, XTALIN, VBUS, XTALOUT
RTC: CS_N, DIN, DOUT, RST_N, SCLK
CLK_PLL: CLK_FIXED, CLK_PROG, CS_N, DIN, SCLK
DBHDR: D[7..0]
LED8: L[7..0]
SW5: D[4..0]
PBCTRL: JTAG, CLK, 1W, SPI_CS_N[1..0], SPARE[1..4]
CONFIG_XCF: DONE, CLK, TMS, DIN, TDO, PROG, INIT, TCK, TDI
AUDIOIF: CS1_N, CS2_N, SCK1, 1WIRE, DIN1, DIN2, SCK2
CS_SPI: CS2, DOUT1, DOUT2, DIN1, CS1, DIN2, SCLK1, EOC1, SCLK2, EOC2

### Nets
AUD_1WIRE: U1#1.D13(IO_L31N_0) ; port AUDIOIF.1WIRE  [project net EXTCTRL.1WIRE]
AUTO_JTAG0: U1#1.Y19(IO_L11N_4) ; port AUTO_JTAG_UBA.DETECT  [project net UBA.DETECT]
AUTO_JTAG1: U1#1.P7(IO_L35P_6) ; port AUTO_JTAG_UBB.DETECT  [project net UBB.DETECT]
AUTO_JTAG2: U1#1.N20(IO_L35P_2) ; harness JTAG_CONFIG.DETECT
AUTO_JTAG3: U1#1.G9(IO_L16N_0) ; harness JTAG_CONFIG.DETECT
AUTO_JTAG4: U1#1.G10(IO/VREF_0) ; harness JTAG_CONFIG.DETECT
AUTO_TCK_HARD0: U1#1.Y12(IO_L27N_5/VREF_5) ; harness JTAG.TCK
AUTO_TCK_HARD1: U1#1.Y7(IO_L06N_6) ; harness JTAG.TCK
AUTO_TCK_HARD2: U1#1.G20(IO_L06N_2) ; harness JTAG.TCK
AUTO_TCK_HARD3: U1#1.L7(IO_L27N_7) ; harness JTAG.TCK
AUTO_TCK_HARD4: U1#1.G15(IO_L27N_1) ; harness JTAG.TCK
AUTO_TCK_SOFT0: U1#1.Y17(IO/VREF_4) ; harness JTAG.TCK
AUTO_TCK_SOFT1: U1#1.T7(IO_L27P_6) ; harness JTAG.TCK
AUTO_TCK_SOFT2: U1#1.L20(IO_L27P_2) ; harness JTAG.TCK
AUTO_TCK_SOFT3: U1#1.G7(IO_L05P_7) ; harness JTAG.TCK
AUTO_TCK_SOFT4: U1#1.G12(IO_L27N_0) ; harness JTAG.TCK
AUTO_TDI_HARD0: U1#1.Y11(IO_L24N_5) ; harness JTAG.TDI
AUTO_TDI_HARD1: U1#1.Y8(IO) ; harness JTAG.TDI
AUTO_TDI_HARD2: U1#1.G19(IO) ; harness JTAG.TDI
AUTO_TDI_HARD3: U1#1.M7(IO_L31N_7) ; harness JTAG.TDI
AUTO_TDI_HARD4: U1#1.G16(IO_L24N_1) ; harness JTAG.TDI
AUTO_TDI_SOFT0: U1#1.Y14(IO_L30N_4/D2) ; harness JTAG.TDI
AUTO_TDI_SOFT1: U1#1.V7(IO_L20N_6) ; harness JTAG.TDI
AUTO_TDI_SOFT2: U1#1.J20(IO_L20N_2) ; harness JTAG.TDI
AUTO_TDI_SOFT3: U1#1.J7(IO_L20P_7) ; harness JTAG.TDI
AUTO_TDI_SOFT4: U1#1.G14(IO_L30N_1) ; harness JTAG.TDI
AUTO_TDO_HARD0: U1#1.Y10(IO_L19P_5/VREF_5) ; harness JTAG.TDO
AUTO_TDO_HARD1: U1#1.Y9(IO_L16P_5) ; harness JTAG.TDO
AUTO_TDO_HARD2: U1#1.G18(IO_L16P_1) ; harness JTAG.TDO
AUTO_TDO_HARD3: U1#1.N7(IO_L35N_7) ; harness JTAG.TDO
AUTO_TDO_HARD4: U1#1.G17(IO_L19P_1) ; harness JTAG.TDO
AUTO_TDO_SOFT0: U1#1.Y16(IO_L24N_4) ; harness JTAG.TDO
AUTO_TDO_SOFT1: U1#1.U7(IO_L20P_6) ; harness JTAG.TDO
AUTO_TDO_SOFT2: U1#1.K20(IO_L20P_2) ; harness JTAG.TDO
AUTO_TDO_SOFT3: U1#1.H7(IO_L10P_7/VREF_7) ; harness JTAG.TDO
AUTO_TDO_SOFT4: U1#1.G13(IO_L30N_0) ; harness JTAG.TDO
AUTO_TMS_HARD0: U1#1.Y13(IO_L30N_5) ; harness JTAG.TMS
AUTO_TMS_HARD1: U1#1.W7(IO_L14N_6) ; harness JTAG.TMS
AUTO_TMS_HARD2: U1#1.H20(IO_L14N_2) ; harness JTAG.TMS
AUTO_TMS_HARD3: U1#1.K7(IO_L20N_7) ; harness JTAG.TMS
AUTO_TMS_HARD4: U1#1.D14(IO_L31N_1/VREF_1) ; harness JTAG.TMS
AUTO_TMS_SOFT0: U1#1.Y18(IO_L16N_4) ; harness JTAG.TMS
AUTO_TMS_SOFT1: U1#1.R7(IO_L31P_6) ; harness JTAG.TMS
AUTO_TMS_SOFT2: U1#1.M20(IO_L31P_2) ; harness JTAG.TMS
AUTO_TMS_SOFT3: U1#1.G8(IO_L11N_0) ; harness JTAG.TMS
AUTO_TMS_SOFT4: U1#1.G11(IO_L24N_0) ; harness JTAG.TMS
BUS_A1: U1#1.Y22(IO_L08P_3)
BUS_A2: U1#1.AF20(IO_L10P_4)
BUS_A3: U1#1.AE19(IO_L15N_4)
BUS_A4: U1#1.AF19(IO_L15P_4)
BUS_A5: U1#1.AE18(IO_L18P_4)
BUS_A6: U1#1.AE17(IO_L23N_4)
BUS_A7: U1#1.AB18(IO_L17N_4)
BUS_A8: U1#1.AB19(IO_L12N_4)
BUS_A9: U1#1.AB20(IO_L09N_4)
BUS_A10: U1#1.AB21(IO_L07N_4)
BUS_A11: U1#1.AD19(IO)
BUS_A12: U1#1.AE20(IO_L10N_4)
BUS_A13: U1#1.AC19(IO_L12P_4)
BUS_A14: U1#1.AC20(IO_L09P_4)
BUS_A15: U1#1.AE21(IO_L08P_4)
BUS_A16: U1#1.AF21(IO)
BUS_A17: U1#1.AC17(IO_L19N_4)
BUS_A18: U1#1.AD17(IO_L22N_4/VREF_4)
BUS_A19: U1#1.AC18(IO_L17P_4)
BUS_A20: U1#1.W23(IO_L17P_3/VREF_3)
BUS_A21: U1#1.AA24(IO_L07N_3)
BUS_A22: U1#1.W24(IO_L17N_3)
BUS_A23: U1#1.U24(IO_L24N_3)
BUS_A24: U1#1.V24(IO_L22P_3)
BUS_D0: U1#1.AB26(IO_L06N_3)
BUS_D1: U1#1.AB25(IO_L06P_3)
BUS_D2: U1#1.AC26(IO_L03N_3)
BUS_D3: U1#1.AC25(IO_L03P_3)
BUS_D4: U1#1.AD25(IO/VREF_4)
BUS_D5: U1#1.AA22(IO_L01N_3/VRP_3)
BUS_D6: U1#1.AB22(IO_L01N_4/VRP_4)
BUS_D7: U1#1.AE24(IO_L04N_4)
BUS_D8: U1#1.AC22(IO_L01P_4/VRN_4)
BUS_D9: U1#1.AD23(IO)
BUS_D10: U1#1.AD10(IO)
BUS_D11: U1#1.AC10(IO_L22N_5)
BUS_D12: U1#1.AA10(IO_L19N_5)
BUS_D13: U1#1.AB23(IO_L02P_3)
BUS_D14: U1#1.AD14(IO_L31P_4/DOUT/BUSY)
BUS_D15: U1#1.AB24(IO_L02N_3/VREF_3)
BUS_D16: U1#1.W16(IO)
BUS_D17: U1#1.AC13(IO_L31N_5/D4)
BUS_D18: U1#1.AD12(IO)
BUS_D19: U1#1.W11(IO_L24P_5)
BUS_D20: U1#1.AC11(IO)
BUS_D21: U1#1.AD9(IO_L18P_5)
BUS_D22: U1#1.AC9(IO)
BUS_D23: U1#1.AD8(IO_L12N_5)
BUS_D24: U1#1.AA6(IO_L05P_5)
BUS_D25: U1#1.AA7(IO)
BUS_D26: U1#1.AA8(IO_L11P_5)
BUS_D27: U1#1.AA9(IO_L16N_5)
BUS_D28: U1#1.AA11(IO_L25P_5)
BUS_D29: U1#1.AA12(IO_L28P_5/D7)
BUS_D30: U1#1.AA13(IO)
BUS_D31: U1#1.W13(IO_L30P_5)
BUS_FLASH_NBUSY: U1#1.AA23(IO_L07P_3) ; port MEM_COMMON.BUS_FLASH_NBUSY  [project net MEM.BUS_FLASH_NBUSY]
BUS_FLASH_NCS: U1#1.Y23(IO_L08N_3) ; port MEM_COMMON.BUS_FLASH_NCS  [project net MEM.BUS_FLASH_NCS]
BUS_FLASH_NRESET: U1#1.V23(IO_L21N_3) ; port MEM_COMMON.BUS_FLASH_NRESET  [project net MEM.BUS_FLASH_NRESET]
BUS_NBE0: U1#1.AF24(IO_L04P_4)
BUS_NBE1: U1#1.AD22(IO_L06N_4/VREF_4)
BUS_NBE2: U1#1.AA14(IO_L30P_4/D3)
BUS_NBE3: U1#1.AA15(IO_L28N_4)
BUS_NOE: U1#1.AC16(IO_L25P_4) ; port MEM_COMMON.BUS_NOE  [project net MEM.BUS_NOE]
BUS_NWE: U1#1.AE23(IO_L05N_4) ; port MEM_COMMON.BUS_NWE  [project net MEM.BUS_NWE]
BUS_SDRAM_CKE: U1#1.AD21(IO_L08N_4) ; port MEM_COMMON.BUS_SDRAM_CKE  [project net MEM.BUS_SDRAM_CKE]
BUS_SDRAM_CLK: NT8.2(Net2) U1#1.AC21(IO_L07P_4) ; port MEM_COMMON.BUS_SDRAM_CLK  [project net MEM.BUS_SDRAM_CLK]
BUS_SDRAM_NCAS: U1#1.AF23(IO_L05P_4) ; port MEM_COMMON.BUS_SDRAM_NCAS  [project net MEM.BUS_SDRAM_NCAS]
BUS_SDRAM_NCS: U1#1.AF22(IO) ; port MEM_COMMON.BUS_SDRAM_NCS  [project net MEM.BUS_SDRAM_NCS]
BUS_SDRAM_NRAS: U1#1.AE22(IO_L06P_4) ; port MEM_COMMON.BUS_SDRAM_NRAS  [project net MEM.BUS_SDRAM_NRAS]
BUS_SRAM_NCS: U1#1.W14(IO_L27P_4/D1) ; port MEM_COMMON.BUS_SRAM_NCS  [project net MEM.BUS_SRAM_NCS]
CCLK: sheet FPGA_PRGSETUP_1/FLASH_CLK, sheet FPGA_CONFIGFLASH_1/CONFIG_XCF.CLK
CLK_ENA: U1#1.V5(IO_L21N_6) ; harness GATE_CLOCKS.EN
CLK_ENB: U1#1.J5(IO_L21P_7) ; harness GATE_CLOCKS.EN
CLK_ENC: U1#1.E5(IO_L01N_0/VRP_0) ; harness GATE_CLOCKS.EN
CLK_EXTA0: U1#1.R5(IO_L32P_6)
CLK_EXTA1: U1#1.T5(IO_L28P_6)
CLK_EXTA2: U1#1.U5(IO_L23P_6)
CLK_EXTB0: U1#1.M5(IO_L32P_7)
CLK_EXTB1: U1#1.L5(IO_L28N_7)
CLK_EXTB2: U1#1.K5(IO_L23N_7)
CLK_EXTC0: U1#1.H5(IO_L16P_7/VREF_7)
CLK_EXTC1: U1#1.G5(IO_L08P_7)
CLK_EXTC2: U1#1.F5(IO_L01N_7/VRP_7)
CLKGEN_CS_N: U1#1.Y1(IO_L10P_6) ; port CLKGEN.CS_N  [project net CLKPLL.CS_N]
CLKGEN_DIN: U1#1.Y2(IO_L10N_6) ; port CLKGEN.DIN  [project net CLKPLL.DIN]
CLKGEN_SCLK: U1#1.AA1(IO_L09P_6) ; port CLKGEN.SCLK  [project net CLKPLL.SCLK]
CSSPI_CS1: U1#1.C12(IO) ; port CSSPI.CS1
CSSPI_CS2: U1#1.AC7(IO_L09N_5) ; port CSSPI.CS2
CSSPI_DIN: U1#1.U4(IO_L24N_6/VREF_6) ; port CSSPI.DIN1
CSSPI_DIN2: U1#1.AD15(IO) ; port CSSPI.DIN2
CSSPI_DOUT: U1#1.W5(IO_L16P_6) ; port CSSPI.DOUT1
CSSPI_DOUT2: U1#1.AD18(IO_L18N_4) ; port CSSPI.DOUT2
CSSPI_EOC1: U1#1.D11(IO_L25P_0) ; port CSSPI.EOC1
CSSPI_EOC2: U1#1.AC8(IO_L12P_5) ; port CSSPI.EOC2
CSSPI_SCLK: U1#1.T4(IO_L33N_6) ; port CSSPI.SCLK1
CSSPI_SCLK2: U1#1.AB13(IO_L31P_5/D5) ; port CSSPI.SCLK2
DAU_CLK.FPGA_CLK1: R1_HOST.2 ; port DAU_CLK.FPGA_CLK1
DAU_FPGA_CLK1: R1_HOST.1 U1#1.L2(IO_L29P_7)
DAU_SPI_CLK: U1#1.E4(IO_L02P_7) ; port DAU_SPI.CLK  [project net DAU_SPI.CLK]
DAU_SPI_DIN: U1#1.F4(IO_L07P_7) ; port DAU_SPI.DIN  [project net DAU_SPI.DIN]
DAU_SPI_DOUT: U1#1.D5(IO_L01P_0/VRN_0) ; port DAU_SPI.DOUT  [project net DAU_SPI.DOUT]
DAU_SPI_MODE: U1#1.F3(IO_L07N_7) ; port DAU_SPI.MODE  [project net DAU_SPI.MODE]
DAU_SPI_SEL: U1#1.E3(IO_L02N_7) ; port DAU_SPI.SEL  [project net DAU_SPI.SEL]
DAU_TFT.BLIGHT: U1#1.AF17(IO_L23P_4)
DAU_TFT.BLUE0: U1#1.AD1(IO_L01P_6/VRN_6)
DAU_TFT.BLUE1: U1#1.AD2(IO_L01N_6/VRP_6)
DAU_TFT.BLUE2: U1#1.AE4(IO_L04N_5)
DAU_TFT.BLUE3: U1#1.AF4(IO)
DAU_TFT.BLUE4: U1#1.AE5(IO_L06N_5)
DAU_TFT.CL1: U1#1.AE11(IO_L26P_5)
DAU_TFT.CL2: U1#1.AF11(IO_L26N_5)
DAU_TFT.CL3: U1#1.AE12(IO_L29P_5/VREF_5)
DAU_TFT.DISP_ON: U1#1.AE16(IO_L26N_4)
DAU_TFT.GREEN0: U1#1.AF6(IO_L08N_5)
DAU_TFT.GREEN1: U1#1.AE7(IO_L10P_5/VRN_5)
DAU_TFT.GREEN2: U1#1.AF7(IO_L10N_5/VRP_5)
DAU_TFT.GREEN3: U1#1.AE8(IO_L15P_5)
DAU_TFT.GREEN4: U1#1.AF8(IO_L15N_5)
DAU_TFT.GREEN5: U1#1.AE9(IO_L18N_5)
DAU_TFT.IRQ: U1#1.AF13(IO/VREF_5)
DAU_TFT.M: U1#1.AF16(IO_L26P_4/VREF_4)
DAU_TFT.MUX: U1#1.AE15(IO_L29N_4)
DAU_TFT.POL: U1#1.AF15(IO_L29P_4)
DAU_TFT.RED0: U1#1.AA2(IO_L09N_6/VREF_6)
DAU_TFT.RED1: U1#1.AB1(IO_L05P_6)
DAU_TFT.RED2: U1#1.AB2(IO_L05N_6)
DAU_TFT.RED3: U1#1.AC1(IO_L03P_6)
DAU_TFT.RED4: U1#1.AC2(IO_L03N_6/VREF_6)
DAU_TFT.STH: U1#1.AF10(IO_L23N_5)
DAU_TFT.STV: U1#1.AE10(IO_L23P_5)
DEBUG_HDRA0: U1#1.V21(IO_L16N_3)
DEBUG_HDRA1: U1#1.U21(IO_L23P_3/VREF_3)
DEBUG_HDRA2: U1#1.T21(IO_L28P_3)
DEBUG_HDRA3: U1#1.R21(IO_L32P_3)
DEBUG_HDRA4: U1#1.P21(IO_L38P_3)
DEBUG_HDRA5: U1#1.P19(IO_L35P_3)
DEBUG_HDRA6: U1#1.N19(IO_L35N_2)
DEBUG_HDRA7: U1#1.N21(IO_L38N_2)
DEBUG_HDRB0: U1#1.W21(IO_L10N_3)
DEBUG_HDRB1: U1#1.Y21(IO_L05N_3)
DEBUG_HDRB2: U1#1.AA21(IO_L01P_3/VRN_3)
DEBUG_HDRB3: U1#1.AA20(IO)
DEBUG_HDRB4: U1#1.AA19(IO_L11P_4)
DEBUG_HDRB5: U1#1.AA18(IO_L16P_4)
DEBUG_HDRB6: U1#1.AA17(IO_L19P_4)
DEBUG_HDRB7: U1#1.AA16(IO_L24P_4)
DONE: sheet FPGA_PRGSETUP_1/FLASH_DONE, sheet FPGA_CONFIGFLASH_1/CONFIG_XCF.DONE
EXTSPI_CSA_N0: U1#1.N2(IO_L40P_7)
EXTSPI_CSA_N1: U1#1.T8(IO_L27N_6)
EXTSPI_CSB_N0: U1#1.M2(IO_L34P_7)
EXTSPI_CSB_N1: U1#1.M1(IO_L34N_7)
EXTSPI_CSC_N0: U1#1.P3(IO_L39P_6)
EXTSPI_CSC_N1: U1#1.P1(IO_L40P_6/VREF_6)
EXTSPI_DIN: U1#1.N5(IO_L38N_7) ; port EXTSPI.DIN  [project net PBSPI.DIN]
EXTSPI_DOUT: U1#1.M8(IO_L31P_7) ; port EXTSPI.DOUT  [project net PBSPI.DOUT]
EXTSPI_SCLK: U1#1.P5(IO_L38P_6) ; port EXTSPI.SCLK  [project net PBSPI.SCLK]
FLASH1_CS_N: U1#1.D21(IO_L07P_1) ; port MEM_SERIALFLASH.FLASH1_CS_N  [project net SFLASH.FLASH1_CS_N]
FLASH2_CS_N: U1#1.C21(IO_L07N_1) ; port MEM_SERIALFLASH.FLASH2_CS_N  [project net SFLASH.FLASH2_CS_N]
FLASH_DIN: U1#1.D22(IO_L01N_1/VRP_1) ; port MEM_SERIALFLASH.DIN  [project net SFLASH.DIN]
FLASH_DOUT: U1#1.D20(IO_L09N_1) ; port MEM_SERIALFLASH.DOUT  [project net SFLASH.DOUT]
FLASH_PROG: sheet FPGA_PRGSETUP_1/FLASH_PROG, sheet FPGA_CONFIGFLASH_1/CONFIG_XCF.PROG
FLASH_SCLK: U1#1.C23(IO_L04P_1) ; port MEM_SERIALFLASH.SCLK  [project net SFLASH.SCLK]
FPGA_CCLK: U1#1.K4(IO_L24P_7) ; port DAU_PROG.CCLK  [project net DAU_PROG.CCLK]
FPGA_CLK: TP2#2.1 U1#1.AD13(IO_L32P_5/GCLK2) ; port DAU_CLK.FPGA_CLK, port CLKGEN.CLK_PROG  [project net CLKPLL.CLK_PROG]
FPGA_DIN: U1#1.K3(IO_L24N_7) ; port DAU_PROG.DIN  [project net DAU_PROG.DIN]
FPGA_DONE: U1#1.N3(IO_L39N_7) ; port DAU_PROG.DONE  [project net DAU_PROG.DONE]
FPGA_ID0: U1#1.C4(IO)
FPGA_ID1: U1#1.C5(IO_L06N_0)
FPGA_ID2: U1#1.D6(IO_L07P_0)
FPGA_ID3: U1#1.D7(IO_L09P_0)
FPGA_INIT: U1#1.L4(IO_L33P_7) ; port DAU_PROG.INIT  [project net DAU_PROG.INIT]
FPGA_INSTALLED: U1#1.G2(IO_L14P_7) ; port DAU_PROG.INSTALLED  [project net DAU_PROG.INSTALLED]
FPGA_M0: U1#1.J4(IO_L21N_7)
FPGA_M1: U1#1.H3(IO_L17N_7)
FPGA_M2: U1#1.H4(IO_L17P_7)
FPGA_PROG_CLK: U1#1.K1(IO_L26N_7) ; port DAU_PROG.PROG_CLK  [project net DAU_PROG.PROG_CLK]
FPGA_PROG_PWR_ON: U1#1.K2(IO_L26P_7) ; port DAU_PROG.PROG_PWR_ON  [project net DAU_PROG.PROG_PWR_ON]
FPGA_PROGRAM: U1#1.J3(IO_L22P_7) ; port DAU_PROG.PROGRAM  [project net DAU_PROG.PROGRAM]
FPGA_TCK: U1#1.L8(IO_L27P_7/VREF_7) ; harness JTAG.TCK
FPGA_TDI: U1#1.G1(IO_L14N_7) ; harness JTAG.TDI
FPGA_TDO: U1#1.G4(IO_L08N_7) ; harness JTAG.TDO
FPGA_TMS: U1#1.M3(IO_L33N_7) ; harness JTAG.TMS
HOST_DIN: U1#1.Y15(IO_L27N_4/DIN/D0) ; sheet FPGA_CONFIGFLASH_1/CONFIG_XCF.DIN
HOST_HARD_TCK: sheet FPGA_PRGSETUP_1/HOST_HARD_TCK, harness JTAG.TCK, sheet FPGA_CONFIGFLASH_1/CONFIG_XCF.TCK
HOST_HARD_TDI: sheet FPGA_PRGSETUP_1/HOST_HARD_TDI, harness JTAG.TDI
HOST_HARD_TDO: harness JTAG.TDO, sheet FPGA_CONFIGFLASH_1/CONFIG_XCF.TDO
HOST_HARD_TMS: sheet FPGA_PRGSETUP_1/HOST_HARD_TMS, harness JTAG.TMS, sheet FPGA_CONFIGFLASH_1/CONFIG_XCF.TMS
HOST_INIT: U1#1.AC14(IO_L31N_4/INIT_B) ; sheet FPGA_CONFIGFLASH_1/CONFIG_XCF.INIT
HOST_LED0: U1#1.Y6(IO_L06P_6)
HOST_LED1: U1#1.W6(IO_L14P_6)
HOST_LED2: U1#1.V6(IO_L16N_6)
HOST_LED3: U1#1.U6(IO_L23N_6)
HOST_LED4: U1#1.T6(IO_L28N_6)
HOST_LED5: U1#1.R6(IO_L32N_6)
HOST_LED6: U1#1.P6(IO_L38N_6)
HOST_LED7: U1#1.P8(IO_L35N_6)
HOST_RESET_SW: U1#1.F1(IO_L09N_7) ; port HOST_RESET_SW
HOST_SOFT_TCK: U1#1.H13(IO_L27P_0) ; harness JTAG.TCK
HOST_SOFT_TDI: U1#1.F14(IO) ; harness JTAG.TDI
HOST_SOFT_TDO: U1#1.H14(IO_L30P_1) ; harness JTAG.TDO
HOST_SOFT_TMS: U1#1.F13(IO_L30P_0) ; harness JTAG.TMS
HOST_TDO_TO_CF_TDI: sheet FPGA_PRGSETUP_1/HOST_TDO_TO_CF_TDI, sheet FPGA_CONFIGFLASH_1/CONFIG_XCF.TDI
HUSB_D0: U1#1.A3(IO)
HUSB_D1: U1#1.B4(IO_L05N_0)
HUSB_D2: U1#1.A4(IO_L05P_0/VREF_0)
HUSB_D3: U1#1.B5(IO_L06P_0)
HUSB_D4: U1#1.A5(IO)
HUSB_D5: U1#1.B6(IO_L08P_0)
HUSB_D6: U1#1.A6(IO)
HUSB_D7: U1#1.B7(IO_L10N_0)
HUSB_D8: U1#1.A15(IO_L29N_1)
HUSB_D9: U1#1.B15(IO_L29P_1)
HUSB_D10: U1#1.A16(IO_L26N_1)
HUSB_D11: U1#1.B16(IO_L26P_1)
HUSB_D12: U1#1.A17(IO_L23N_1)
HUSB_D13: U1#1.B17(IO_L23P_1)
HUSB_D14: U1#1.B18(IO_L18N_1)
HUSB_D15: U1#1.A19(IO_L15N_1)
HUSB_FIFOADR0: U1#1.A11(IO_L26P_0/VREF_0) ; port USB_INTERFACE.FIFOADR0  [project net USB.FIFOADR0]
HUSB_FIFOADR1: U1#1.B12(IO_L29N_0) ; port USB_INTERFACE.FIFOADR1  [project net USB.FIFOADR1]
HUSB_FIFOADR2: U1#1.B11(IO_L26N_0) ; port USB_INTERFACE.FIFOADR2  [project net USB.FIFOADR2]
HUSB_FLAGA: U1#1.A7(IO_L10P_0) ; port USB_INTERFACE.FLAGA  [project net USB.FLAGA]
HUSB_FLAGB: U1#1.B8(IO_L15N_0) ; port USB_INTERFACE.FLAGB  [project net USB.FLAGB]
HUSB_FLAGC: U1#1.A8(IO_L15P_0) ; port USB_INTERFACE.FLAGC  [project net USB.FLAGC]
HUSB_FLAGD_CS_N: U1#1.A14(IO) ; port USB_INTERFACE.FLAGD_CS_N  [project net USB.FLAGD_CS_N]
HUSB_IFCLK: U1#1.B3(IO/VREF_0) ; port USB_INTERFACE.IFCLK  [project net USB.IFCLK]
HUSB_INT_N: U1#1.B10(IO_L23N_0) ; port USB_INTERFACE.INT_N  [project net USB.INT_N]
HUSB_PKTEND: U1#1.A12(IO_L29P_0) ; port USB_INTERFACE.PKTEND  [project net USB.PKTEND]
HUSB_RD_N: U1#1.B19(IO_L15P_1) ; port USB_INTERFACE.RD_N  [project net USB.RD_N]
HUSB_READY: U1#1.B9(IO_L18P_0) ; port USB_INTERFACE.READY  [project net USB.READY]
HUSB_RESET_N: U1#1.A21(IO_L08N_1) ; port USB_INTERFACE.RESET_N  [project net USB.RESET_N]
HUSB_SLOE: U1#1.A10(IO_L23P_0) ; port USB_INTERFACE.SLOE  [project net USB.SLOE]
HUSB_VBUS: U1#1.D1(IO_L03N_7/VREF_7) ; port USB_INTERFACE.VBUS  [project net USB.VBUS]
HUSB_WR_N: U1#1.A20(IO_L10N_1/VREF_1) ; port USB_INTERFACE.WR_N  [project net USB.WR_N]
LED_CS1_N: U1#1.F19(IO_L11P_1) ; port AUDIOIF.CS1_N  [project net EXTCTRL.CS1_N]
LED_CS2_N: U1#1.F18(IO_L16N_1) ; port AUDIOIF.CS2_N  [project net EXTCTRL.CS2_N]
LED_DIN1: U1#1.F21(IO_L05P_1) ; port AUDIOIF.DIN1  [project net EXTCTRL.DIN1]
LED_DIN2: U1#1.F16(IO_L25P_1) ; port AUDIOIF.DIN2  [project net EXTCTRL.DIN2]
LED_SCK1: U1#1.F20(IO) ; port AUDIOIF.SCK1  [project net EXTCTRL.SCK1]
LED_SCK2: U1#1.F17(IO_L19N_1) ; port AUDIOIF.SCK2  [project net EXTCTRL.SCK2]
LINEOUT_HOSTL: U1#1.D8(IO_L12P_0) ; port AUDIO_OUT_HOST.L  [project net AOUT_HOST.L]
LINEOUT_HOSTR: U1#1.C8(IO) ; port AUDIO_OUT_HOST.R  [project net AOUT_HOST.R]
MASTER_CNCT: U1#1.F12(IO_L28N_0) ; harness NANOTALK_JTAG.CNCT
MASTER_MODE: U1#1.F6(IO_L01P_7/VRN_7) ; harness NANOTALK_JTAG.MODE
MASTER_TCK: U1#1.F7(IO/VREF_0) ; harness NANOTALK_JTAG.TCK
MASTER_TDI: U1#1.F10(IO_L19N_0) ; harness NANOTALK_JTAG.TDI
MASTER_TDO: U1#1.F11(IO_L24P_0) ; harness NANOTALK_JTAG.TDO
MASTER_TMS: U1#1.F9(IO_L16P_0) ; harness NANOTALK_JTAG.TMS
NEXUS_TCK: U1#1.H1(IO_L19N_7/VREF_7) ; harness JTAG.TCK
NEXUS_TDI: U1#1.J2(IO_L22N_7) ; harness JTAG.TDI
NEXUS_TDO: U1#1.N4(IO_L39P_7) ; harness JTAG.TDO
NEXUS_TMS: U1#1.H2(IO_L19P_7) ; harness JTAG.TMS
ONE_WIRE_DBID: U1#1.R3(IO_L33P_6) ; port ONE_WIRE_DBID  [project net 1W_DBID]
ONE_WIRE_NBID: U1#1.D2(IO_L03P_7) ; port ONE_WIRE_NBID  [project net 1W_NBID]
ONE_WIRE_PB_ID_A: U1#1.N1(IO_L40N_7/VREF_7) ; harness ONE_WIRE.ID
ONE_WIRE_PB_ID_B: U1#1.P4(IO_L39N_6) ; harness ONE_WIRE.ID
ONE_WIRE_PB_ID_C: U1#1.R2(IO_L34N_6/VREF_6) ; harness ONE_WIRE.ID
ONE_WIRE_PIOA1: U1#1.C10(IO_L22P_0)
ONE_WIRE_PIOA2: U1#1.D10(IO_L22N_0)
ONE_WIRE_PIOB1: U1#1.C9(IO_L18N_0)
ONE_WIRE_PIOB2: U1#1.D9(IO_L17P_0)
ONE_WIRE_PIOC1: U1#1.F2(IO_L09P_7)
ONE_WIRE_PIOC2: U1#1.E1(IO_L06N_7)
PB_SPAREA1: U1#1.A22(IO)
PB_SPAREA2: U1#1.D16(IO)
PB_SPAREA3: U1#1.B22(IO_L06N_1/VREF_1)
PB_SPAREA4: U1#1.C15(IO/VREF_1)
PB_SPAREB1: U1#1.D17(IO_L22N_1)
PB_SPAREB2: U1#1.C17(IO/VREF_1)
PB_SPAREB3: U1#1.C18(IO_L18P_1)
PB_SPAREB4: U1#1.D18(IO/VREF_1)
PB_SPAREC1: U1#1.C19(IO_L12N_1)
PB_SPAREC2: U1#1.D19(IO_L12P_1)
PB_SPAREC3: U1#1.B23(IO_L04N_1)
PB_SPAREC4: U1#1.E2(IO_L06P_7)
PP_ACK: U1#1.E11(IO_L25N_0) ; port PPRT.ACK  [project net PPRT.ACK]
PP_AUTOFD: U1#1.E22(IO_L01P_1/VRN_1) ; port PPRT.AUTOFD  [project net PPRT.AUTOFD]
PP_BUSY: U1#1.E10(IO_L19P_0) ; port PPRT.BUSY  [project net PPRT.BUSY]
PP_D0: U1#1.E21(IO_L05N_1)
PP_D1: U1#1.E18(IO)
PP_D2: U1#1.E16(IO_L25N_1)
PP_D3: U1#1.H15(IO_L27P_1)
PP_D4: U1#1.E14(IO_L31P_1)
PP_D5: U1#1.E13(IO)
PP_D6: U1#1.H12(IO)
PP_D7: U1#1.E12(IO_L28P_0)
PP_ERROR: U1#1.E20(IO_L09P_1) ; port PPRT.ERROR  [project net PPRT.ERROR]
PP_INIT: U1#1.E19(IO_L11N_1) ; port PPRT.INIT  [project net PPRT.INIT]
PP_PE: U1#1.E9(IO_L17N_0) ; port PPRT.PE  [project net PPRT.PE]
PP_PLUG: U1#1.E15(IO_L28N_1) ; port PPRT.PLUG  [project net PPRT.PLUG]
PP_SELECT: U1#1.E17(IO_L22P_1) ; port PPRT.SELECT  [project net PPRT.SELECT]
PP_SELECT_IN: U1#1.E8(IO_L12N_0) ; port PPRT.SELECTIN  [project net PPRT.SELECTIN]
PP_STROBE: U1#1.G22(IO_L08N_2) ; port PPRT.STROBE  [project net PPRT.STROBE]
REF_CLK: TP1.1 U1#1.AE13(IO_L32N_5/GCLK3) ; port DAU_CLK.REF_CLK, port CLKGEN.CLK_FIXED  [project net CLKPLL.CLK_FIXED]
RTC_CS_N: U1#1.J22(IO_L21N_2) ; port RTC.CS_N  [project net RTC.CS_N]
RTC_DIN: U1#1.M22(IO_L32P_2) ; port RTC.DIN  [project net RTC.DIN]
RTC_DOUT: U1#1.L22(IO_L28P_2) ; port RTC.DOUT  [project net RTC.DOUT]
RTC_RST_N: U1#1.M19(IO_L31N_2) ; port RTC.RST_N  [project net RTC.RST_N]
RTC_SCLK: U1#1.K22(IO_L23P_2) ; port RTC.SCLK  [project net RTC.SCLK]
SD_CLK: U1#1.K6(IO_L23P_7) ; port SD.CLK  [project net SD.CLK]
SD_CMD: U1#1.J6(IO_L16N_7) ; port SD.CMD  [project net SD.CMD]
SD_DAT0: U1#1.M6(IO_L32N_7)
SD_DAT1: U1#1.N6(IO_L38P_7)
SD_DAT2: U1#1.G6(IO_L05N_7)
SD_DAT3: U1#1.H6(IO_L10N_7)
SD_DETECT: U1#1.L6(IO_L28P_7) ; port SD.DETECT  [project net SD.DETECT]
SD_PROTECT: U1#1.N8(IO_L35P_7) ; port SD.PROTECT  [project net SD.PROTECT]
SDRAM_FEEDBACK: NT8.1(Net1) U1#1.AF14(IO_L32P_4/GCLK0)
SLAVE_CNCT: U1#1.G21(IO_L06P_2) ; harness NANOTALK_JTAG.CNCT
SLAVE_MODE: U1#1.H21(IO_L14P_2) ; harness NANOTALK_JTAG.MODE
SLAVE_TCK: U1#1.K21(IO_L23N_2/VREF_2) ; harness NANOTALK_JTAG.TCK
SLAVE_TDI: U1#1.L21(IO_L28N_2) ; harness NANOTALK_JTAG.TDI
SLAVE_TDO: U1#1.M21(IO_L32N_2) ; harness NANOTALK_JTAG.TDO
SLAVE_TMS: U1#1.J21(IO_L16P_2) ; harness NANOTALK_JTAG.TMS
SRAM_A0: U1#1.J23(IO_L21P_2)
SRAM_A1: U1#1.H24(IO_L17P_2/VREF_2)
SRAM_A2: U1#1.J24(IO_L22N_2)
SRAM_A3: U1#1.K24(IO_L24P_2)
SRAM_A4: U1#1.K23(IO_L24N_2)
SRAM_A5: U1#1.L19(IO_L27N_2)
SRAM_A6: U1#1.N24(IO_L39P_2)
SRAM_A7: U1#1.N23(IO_L39N_2)
SRAM_A8: U1#1.P23(IO_L39P_3)
SRAM_A9: U1#1.P24(IO_L39N_3)
SRAM_A10: U1#1.H23(IO_L17N_2)
SRAM_A11: U1#1.G23(IO_L08P_2)
SRAM_A12: U1#1.F24(IO_L07P_2)
SRAM_A13: U1#1.F23(IO_L07N_2)
SRAM_A14: U1#1.E24(IO_L02P_2)
SRAM_A15: U1#1.T23(IO_L33P_3)
SRAM_A16: U1#1.R24(IO_L33N_3)
SRAM_A17: U1#1.T19(IO_L27P_3)
SRAM_A18: U1#1.E23(IO_L02N_2)
SRAM_D0: U1#1.M25(IO_L34N_2/VREF_2)
SRAM_D1: U1#1.L26(IO_L29P_2)
SRAM_D2: U1#1.L25(IO_L29N_2)
SRAM_D3: U1#1.K26(IO_L26P_2)
SRAM_D4: U1#1.K25(IO_L26N_2)
SRAM_D5: U1#1.J25(IO_L22P_2)
SRAM_D6: U1#1.H26(IO_L19P_2)
SRAM_D7: U1#1.H25(IO_L19N_2)
SRAM_D8: U1#1.G26(IO_L10P_2)
SRAM_D9: U1#1.G25(IO_L10N_2)
SRAM_D10: U1#1.F26(IO_L09P_2)
SRAM_D11: U1#1.F25(IO_L09N_2/VREF_2)
SRAM_D12: U1#1.E26(IO_L05P_2)
SRAM_D13: U1#1.E25(IO_L05N_2)
SRAM_D14: U1#1.D26(IO_L03P_2)
SRAM_D15: U1#1.D25(IO_L03N_2/VREF_2)
SRAM_D16: U1#1.AA25(IO_L09P_3/VREF_3)
SRAM_D17: U1#1.AA26(IO_L09N_3)
SRAM_D18: U1#1.Y25(IO_L14P_3)
SRAM_D19: U1#1.Y26(IO_L14N_3)
SRAM_D20: U1#1.W25(IO_L19P_3)
SRAM_D21: U1#1.W26(IO_L19N_3)
SRAM_D22: U1#1.V25(IO_L22N_3)
SRAM_D23: U1#1.U25(IO_L26P_3)
SRAM_D24: U1#1.U26(IO_L26N_3)
SRAM_D25: U1#1.T25(IO_L29P_3)
SRAM_D26: U1#1.T26(IO_L29N_3)
SRAM_D27: U1#1.R25(IO_L34P_3/VREF_3)
SRAM_D28: U1#1.R26(IO_L34N_3)
SRAM_D29: U1#1.P25(IO_L40P_3)
SRAM_D30: U1#1.P26(IO_L40N_3/VREF_3)
SRAM_D31: U1#1.N26(IO_L40P_2/VREF_2)
SRAM_NBE0: U1#1.C26(IO_L01P_2/VRN_2)
SRAM_NBE1: U1#1.C25(IO_L01N_2/VRP_2)
SRAM_NBE2: U1#1.M26(IO_L34P_2)
SRAM_NBE3: U1#1.N25(IO_L40N_2)
SRAM_NCS: U1#1.L23(IO_L33N_2) ; port MEM_SRAM.NCS  [project net SRAM.NCS]
SRAM_NOE: U1#1.U23(IO_L24P_3) ; port MEM_SRAM.NOE  [project net SRAM.NOE]
SRAM_NWE: U1#1.M24(IO_L33P_2) ; port MEM_SRAM.NWE  [project net SRAM.NWE]
SW_DB0: U1#1.R8(IO_L31N_6)  [project net SW0]
SW_DB1: U1#1.E7(IO_L09N_0)  [project net SW1]
SW_DB2: U1#1.E6(IO_L07N_0)  [project net SW2]
SW_DB3: U1#1.C6(IO_L08N_0)  [project net SW3]
SW_DB4: U1#1.H11(IO)  [project net SW4]
SW_USER0: U1#1.T22(IO_L28N_3)
SW_USER1: U1#1.R22(IO_L32N_3)
SW_USER2: U1#1.R19(IO_L31P_3)
SW_USER3: U1#1.P22(IO_L38N_3)
SW_USER4: U1#1.N22(IO_L38P_2)
TFT.BLIGHT: U1#1.W12(IO_L27P_5)
TFT.BLUE0: U1#1.AB12(IO_L28N_5/D6)
TFT.BLUE1: U1#1.AB11(IO_L25N_5)
TFT.BLUE2: U1#1.AB10(IO_L22P_5)
TFT.BLUE3: U1#1.AB9(IO)
TFT.BLUE4: U1#1.AB8(IO_L11N_5/VREF_5)
TFT.CL1: U1#1.AB5(IO_L01P_5/CS_B)
TFT.CL2: U1#1.Y5(IO_L08N_6)
TFT.CL3: U1#1.AC6(IO_L07P_5)
TFT.DISP_ON: U1#1.AD6(IO_L07N_5)
TFT.GREEN0: U1#1.Y4(IO_L08P_6)
TFT.GREEN1: U1#1.W4(IO_L17N_6)
TFT.GREEN2: U1#1.W3(IO_L17P_6/VREF_6)
TFT.GREEN3: U1#1.V4(IO_L21P_6)
TFT.GREEN4: U1#1.V3(IO_L22N_6)
TFT.GREEN5: U1#1.U3(IO_L24P_6)
TFT.IRQ: U1#1.W2(IO_L19N_6)
TFT.M: U1#1.AB6(IO_L05N_5)
TFT.POL: U1#1.AB7(IO_L09P_5)
TFT.RED0: U1#1.AD4(IO_L04P_5)
TFT.RED1: U1#1.AB4(IO_L02N_6)
TFT.RED2: U1#1.AB3(IO_L02P_6)
TFT.RED3: U1#1.AA4(IO_L07N_6)
TFT.RED4: U1#1.AA3(IO_L07P_6)
TFT.STH: U1#1.AC5(IO_L01N_5/RDWR_B)
TFT.STV: U1#1.AD5(IO_L06P_5)
TFT_SPI.BUSY: U1#1.U2(IO_L26N_6)
TFT_SPI.CLK: U1#1.R1(IO_L34P_6)
TFT_SPI.CS_N: U1#1.T1(IO_L29P_6)
TFT_SPI.DIN: U1#1.U1(IO_L26P_6)
TFT_SPI.DOUT: U1#1.W1(IO_L19P_6)
UGCLK0: U1#1.B13(IO_L32N_0/GCLK7)
UGCLK1: U1#1.A13(IO_L32P_0/GCLK6)
UGCLK2: U1#1.C14(IO_L32P_1/GCLK4)
UGCLK3: U1#1.B14(IO_L32N_1/GCLK5)
UGCLK4: U1#1.AE14(IO_L32N_4/GCLK1)

Not connected (* = marked no-connect by the designer): U1#1 A23(IO)* AA5(NC)* AB14(IO/VREF_4)* AB15(IO_L28P_4)* AB16(IO_L25N_4)* AB17(IO_L22P_4)* AE6(IO_L08P_5)* AF5(IO/VREF_5)* AF12(IO_L29N_5)* B20(IO_L10P_1)* B21(IO_L08P_1)* C13(IO_L31P_0/VREF_0)* C22(IO_L06P_1)* F8(IO_L11P_0)* F15(IO_L28P_1)* F22(NC)* H16(IO_L24P_1)* H22(IO_L16N_2)* L1(IO_L29N_7)* P2(IO_L40N_6)* P20(IO_L35N_3)* R20(IO_L31N_3)* T2(IO_L29N_6)* T20(IO_L27N_3)* U20(IO_L20N_3)* U22(IO_L23N_3)* V2(IO_L22P_6)* V20(IO_L20P_3)* V22(IO_L21P_3)* W15(IO)* W20(IO_L10P_3)* W22(IO_L16P_3)* Y20(IO_L05P_3)*

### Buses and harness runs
bus BUS_A[24..1]
bus BUS_D[31..0]
bus BUS_NBE[3..0]
bus CLK_EXTA[2..0]
bus CLK_EXTB[2..0]
bus CLK_EXTC[2..0]
bus DEBUG_HDRA[7..0]
bus DEBUG_HDRB[7..0]
bus EXTSPI_CSA_N[1..0]
bus EXTSPI_CSB_N[1..0]
bus EXTSPI_CSC_N[1..0]
bus FPGA_ID[3..0]
bus FPGA_M[2..0]
bus HOST_LED[7..0]
bus HUSB_D[15..0]
bus ONE_WIRE_PIOA[1..2]
bus ONE_WIRE_PIOB[1..2]
bus ONE_WIRE_PIOC[1..2]
bus PB_SPAREA[1..4]
bus PB_SPAREB[1..4]
bus PB_SPAREC[1..4]
bus PP_D[7..0]
bus SD_DAT[3..0]
bus SRAM_A[18..0]
bus SRAM_D[31..0]
bus SRAM_NBE[3..0]
bus SW_DB[4..0]
bus SW_USER[4..0]
harness DAU_TFT = port DAU_TFT
harness TFT = port TFT
harness TFT_SPI = port TFT_SPI

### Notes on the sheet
- ONE WIRE ID
- HOST DEBUG PORTS
- HOST PERIPHERALS
- PB A - Control
- DAUGHTER BD JTAG
- USB2
- Current Sense
- DAUGHTER BD PROGRAM
- Host Reset
- Status LEDs
- PB B - Control
- FPGA SUPPORT
- DAUGHTER BD SPI BUS
- SD Card
- DELTA-SIGMAL AUDIO
- DAUGHTER BD CLOCKS
- NOTE:
- USER JTAG A+B (AUTO)
- PARALLEL PORT
- PB C - Control
- PBs - SPI BUSES
- (near NT8) We use seperate lines for SCLK, DIN, DOUT even though they could be common because they are tristates controlled by thechip-selects.
  This makes the board routing easier (and we have enough pins) since the targets are all in different physical locations.
  These will ultimately be commoned inside the FPGA because the SPI state machine, controlled by the host and the daughter-board, assumes single DOUT, DIN
- RTC - SPI
- NANOTALK
- AUDIO BOARD I/F
- HOST JTAG
- TFT LCD DISPLAY INTERFACE
- CONTROL TO/FROM TFT
- TFT FROM DAUGHTER BOARD

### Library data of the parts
NT8 = D-002-0002: Net-Tie, Surface Mount, 2 x 0.4mm x 0.2mm SMT Pads - For 0.2mm Track
R1_HOST = D-100-0085: Resistor, 5R6 1% 0402 (1005); Power Rating: 63 mW; Resistance: 5.6 R
TP1 TP2#2 = D-006-0000: as TP2#1 on sheet PWJACK+SWITCH
U1#1 = D-241-0001: FPGA, Xilinx Spartan3-1500 FG676 Speed=4; EnablePinSwap: True; Supply Voltage: mV

## Sheet FPGA_PRGSETUP.SchDoc: XC3S1500-4FG676C Configuration
size A4; Organization: Altium Limited.; Address1: Level 3, 12a Rodborough Rd; Address2: Frenchs Forest 2086; Address3: NSW; Address4: AUSTRALIA; DocumentNumber: 13; Revision: 6; SheetNumber: 13; SheetTotal: 64; PageSetup: Record=PageOptions|CenterHorizontal=True|CenterVertical=True|PrintScale=0.97|XCorrection=1.00|YCorrection=1.00|PrintKind=0|BorderSize=5000000|LeftOffset=0|BottomOffset=0|Orientation=2|PaperLength=1000|PaperWidth=1000|Scale=100|PaperSource=7|PrintQuality=-4|MediaType=1|DitherType=10|PaperKind=A4 (210 x 297mm)|PrintScaleMode=1
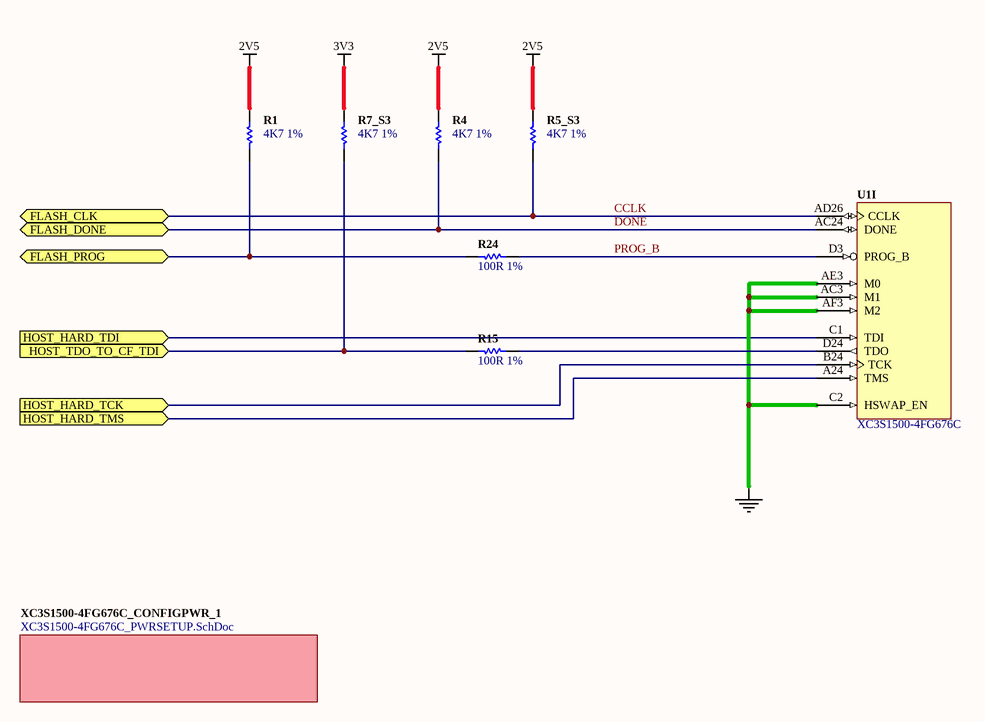
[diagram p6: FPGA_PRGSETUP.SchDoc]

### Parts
(Parts that share a designator on the sheet are numbered #1, #2 ... from top to bottom, then left to right.)
R1  4K7 1%  [RESC1005-STAR]
R4  4K7 1%  [RESC1005-STAR]
R5_S3  4K7 1%  [RESC1005-STAR]
R7_S3  4K7 1%  [RESC1005-STAR]
R15  100R 1%  [RESC1005-STAR]
R24  100R 1%  [RESC1005-STAR]
U1#1  XC3S1500-4FG676C  [BGA100P26X26-676]  (part I of 12)

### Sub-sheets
XC3S1500-4FG676C_CONFIGPWR_1 = XC3S1500-4FG676C_PWRSETUP.SchDoc: no entries

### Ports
FLASH_CLK (bidir), FLASH_DONE (bidir), FLASH_PROG (bidir), HOST_HARD_TCK (in), HOST_HARD_TDI (in), HOST_HARD_TMS (in), HOST_TDO_TO_CF_TDI (in)

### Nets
2V5: R1.1 R4.1 R5_S3.1
3V3: R7_S3.1
GND: U1#1.AC3(M1) U1#1.AE3(M0) U1#1.AF3(M2) U1#1.C2(HSWAP_EN)
CCLK: R5_S3.2 U1#1.AD26(CCLK) ; port FLASH_CLK
DONE: R4.2 U1#1.AC24(DONE) ; port FLASH_DONE
FLASH_PROG: R1.2 R24.2 ; port FLASH_PROG
HOST_HARD_TCK: U1#1.B24(TCK) ; port HOST_HARD_TCK
HOST_HARD_TDI: U1#1.C1(TDI) ; port HOST_HARD_TDI
HOST_HARD_TMS: U1#1.A24(TMS) ; port HOST_HARD_TMS
HOST_TDO_TO_CF_TDI: R7_S3.2 R15.2 ; port HOST_TDO_TO_CF_TDI
PROG_B: R24.1 U1#1.D3(PROG_B)
NetR15_1: R15.1 U1#1.D24(TDO)

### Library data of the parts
R1 R4 R5_S3 R7_S3 = D-100-0088: Resistor, 4K7 1% 0402 (1005); Power Rating: 63 mW; Resistance: 4.7 K
R15 R24 = D-100-0131: Resistor, 100R 1% 0402 (1005); Power Rating: 63 mW
U1#1 = D-241-0001: as U1#1 on sheet Host_FPGA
